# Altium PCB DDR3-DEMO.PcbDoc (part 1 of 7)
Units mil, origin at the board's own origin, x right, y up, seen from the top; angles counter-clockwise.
Board outline 2827 x 2165.35 mil, 8 copper layers (TOP, GND02, ART03, ART04, PWR05, ART06, GND07, BOTTOM); 111 components, 133 nets, 5542 pads, 873 vias.
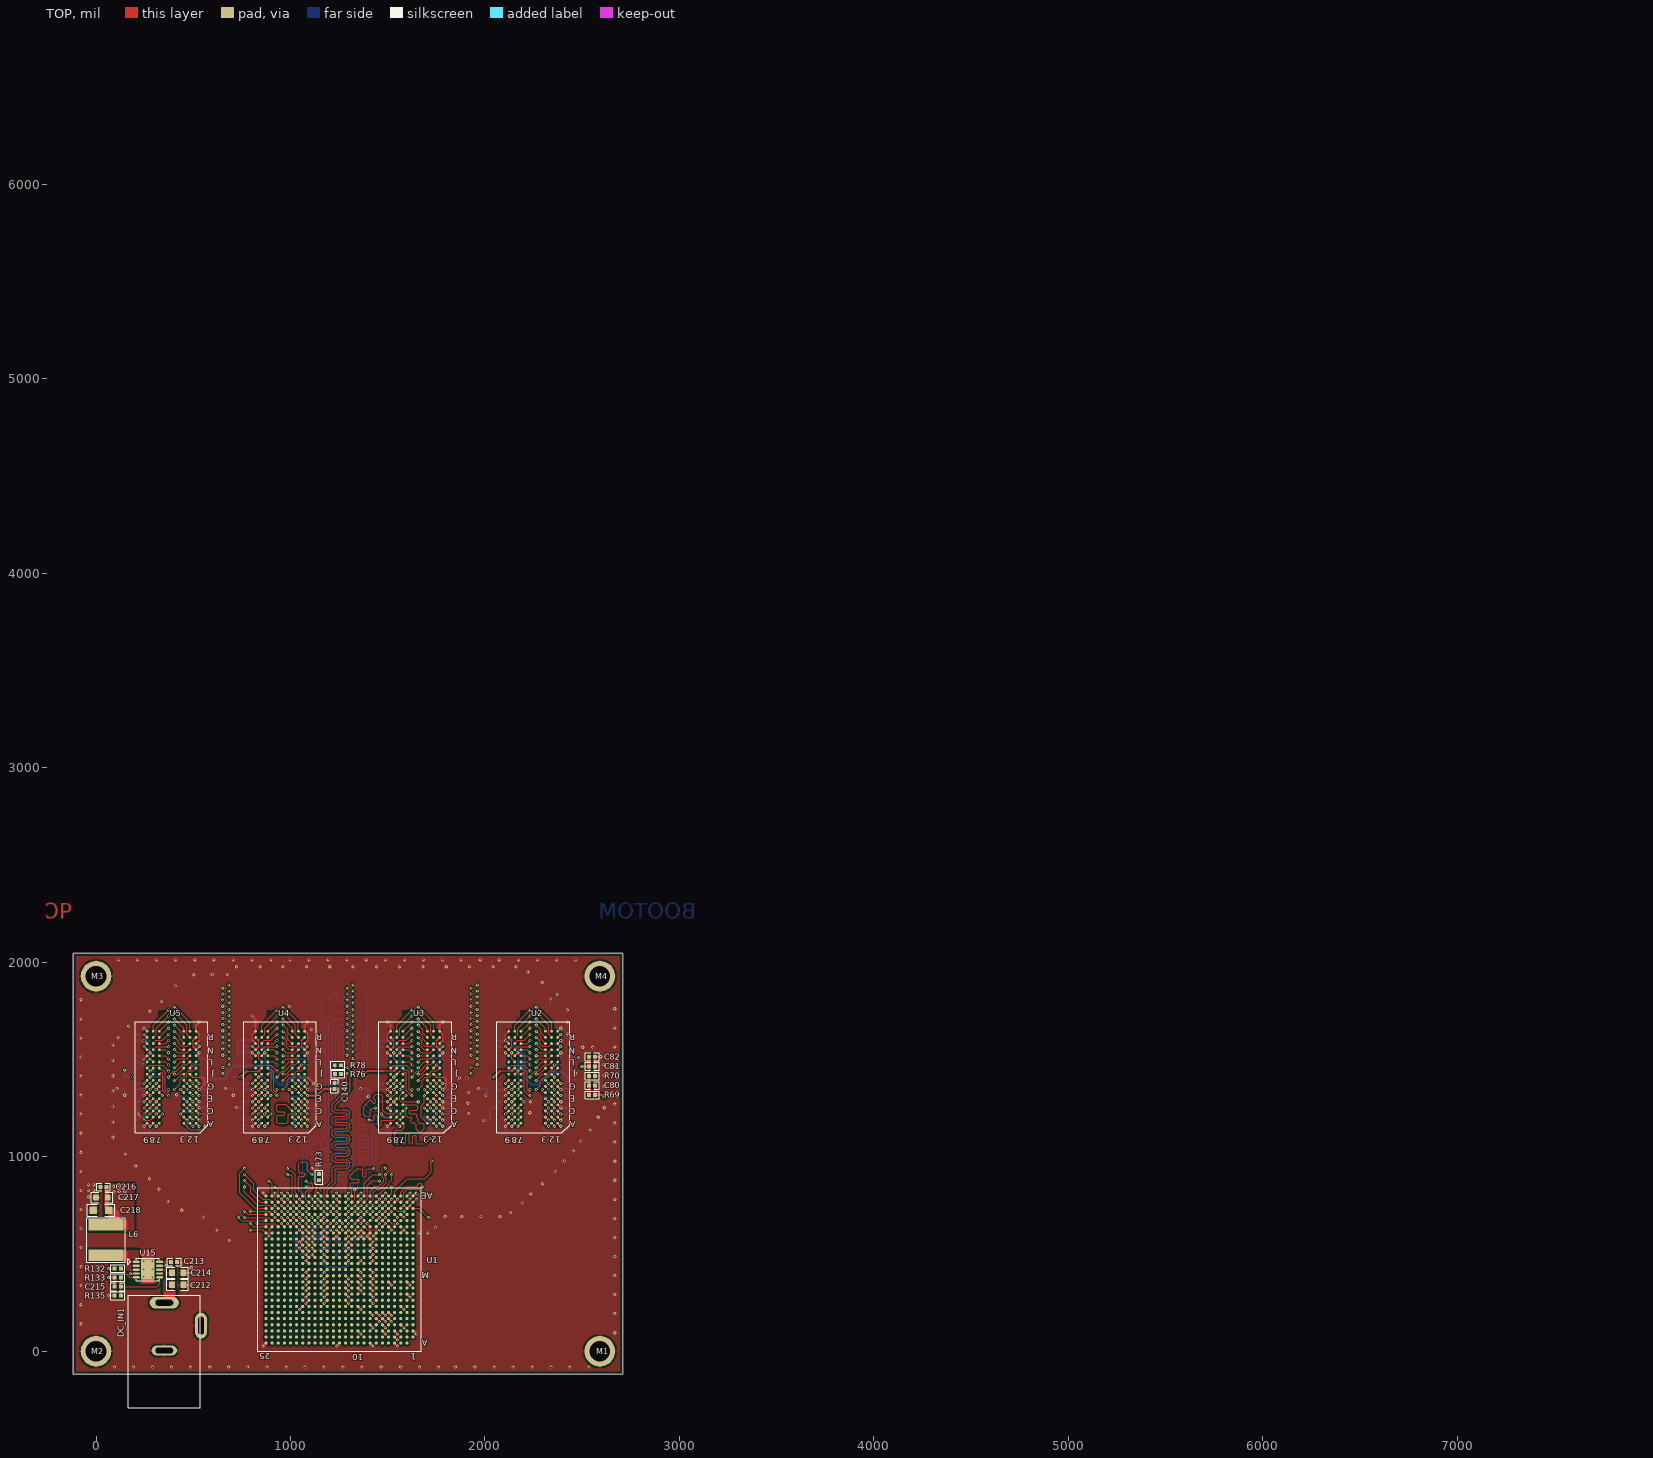
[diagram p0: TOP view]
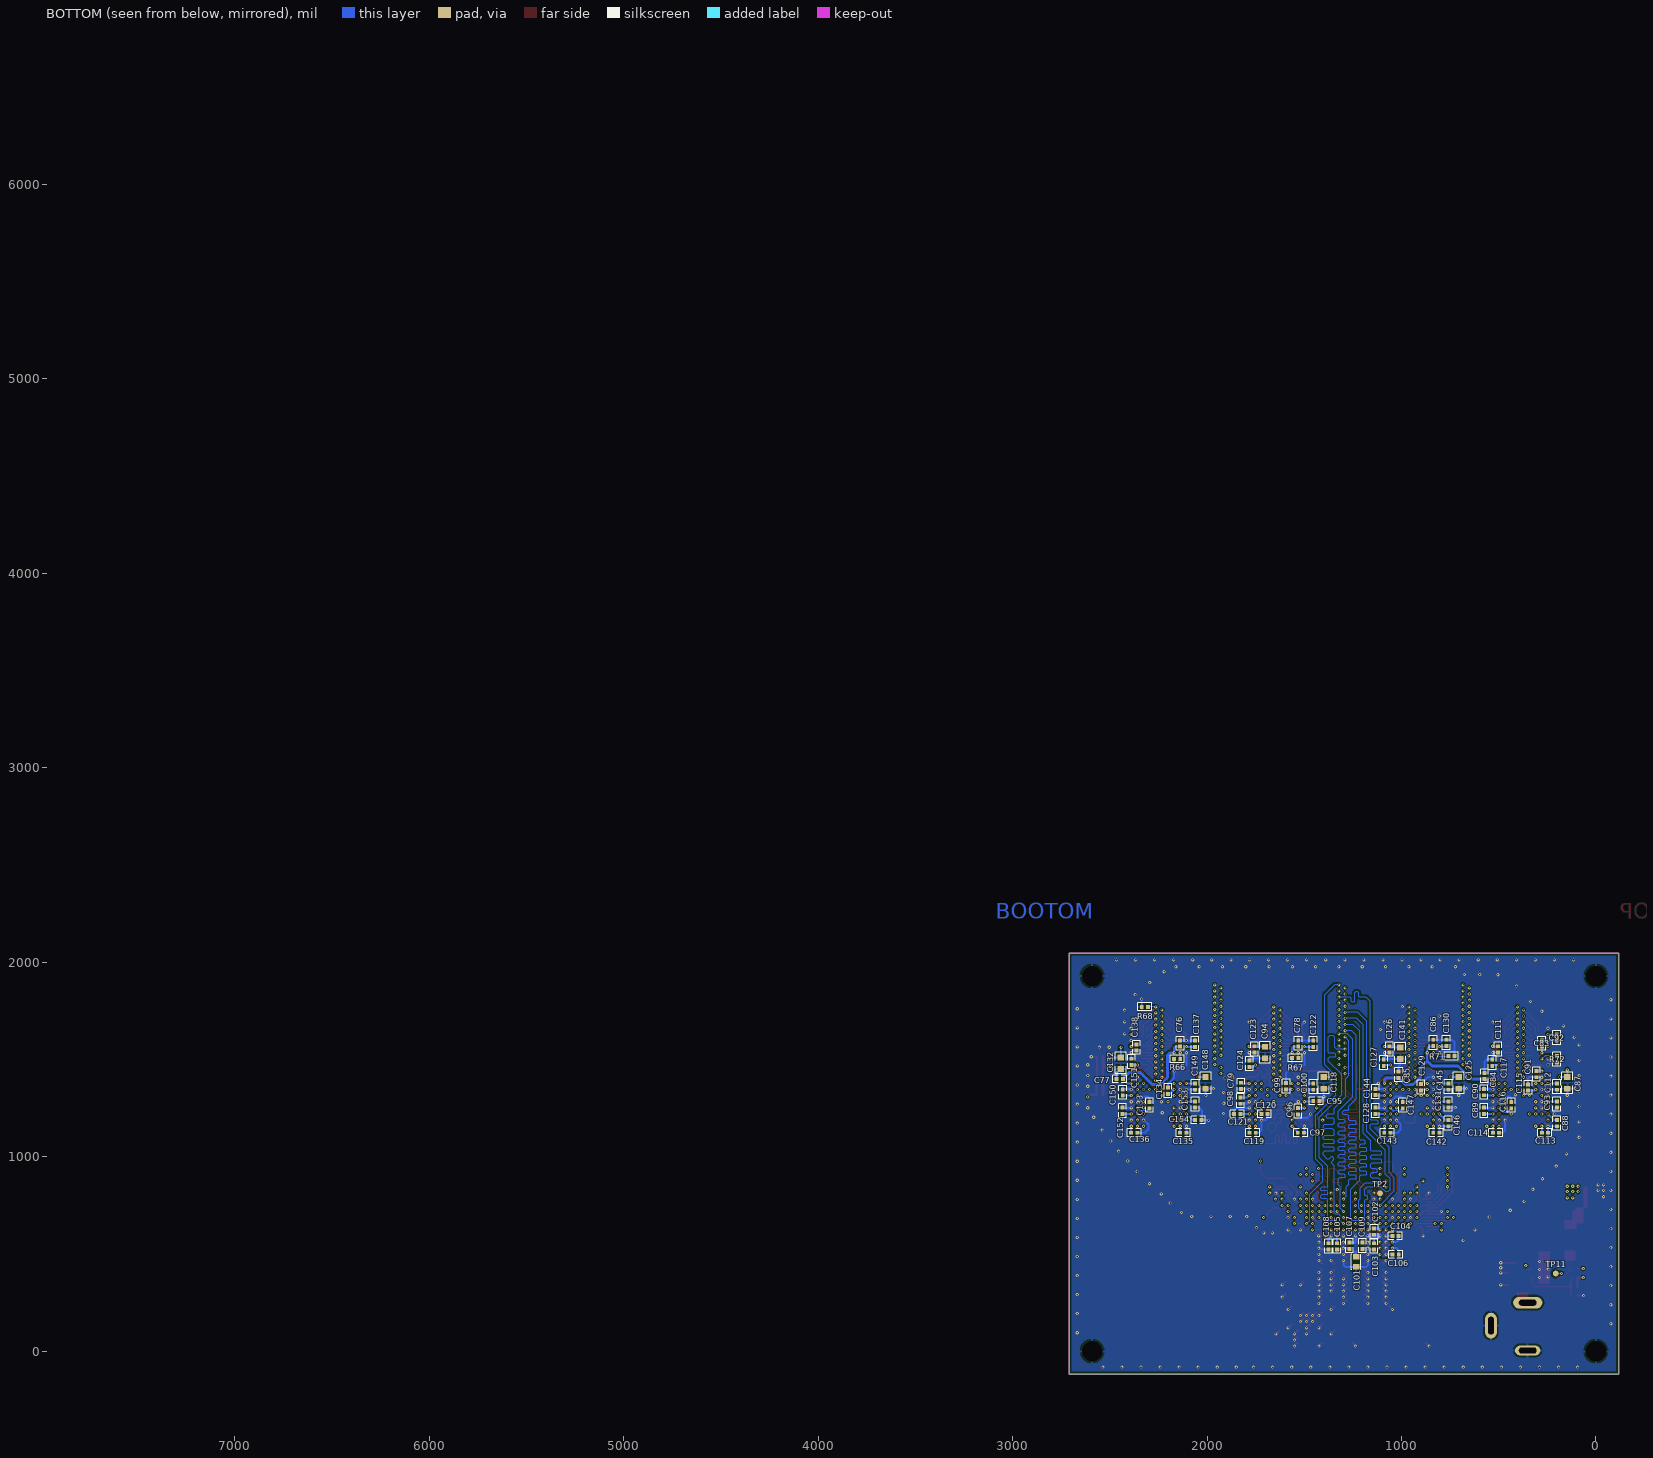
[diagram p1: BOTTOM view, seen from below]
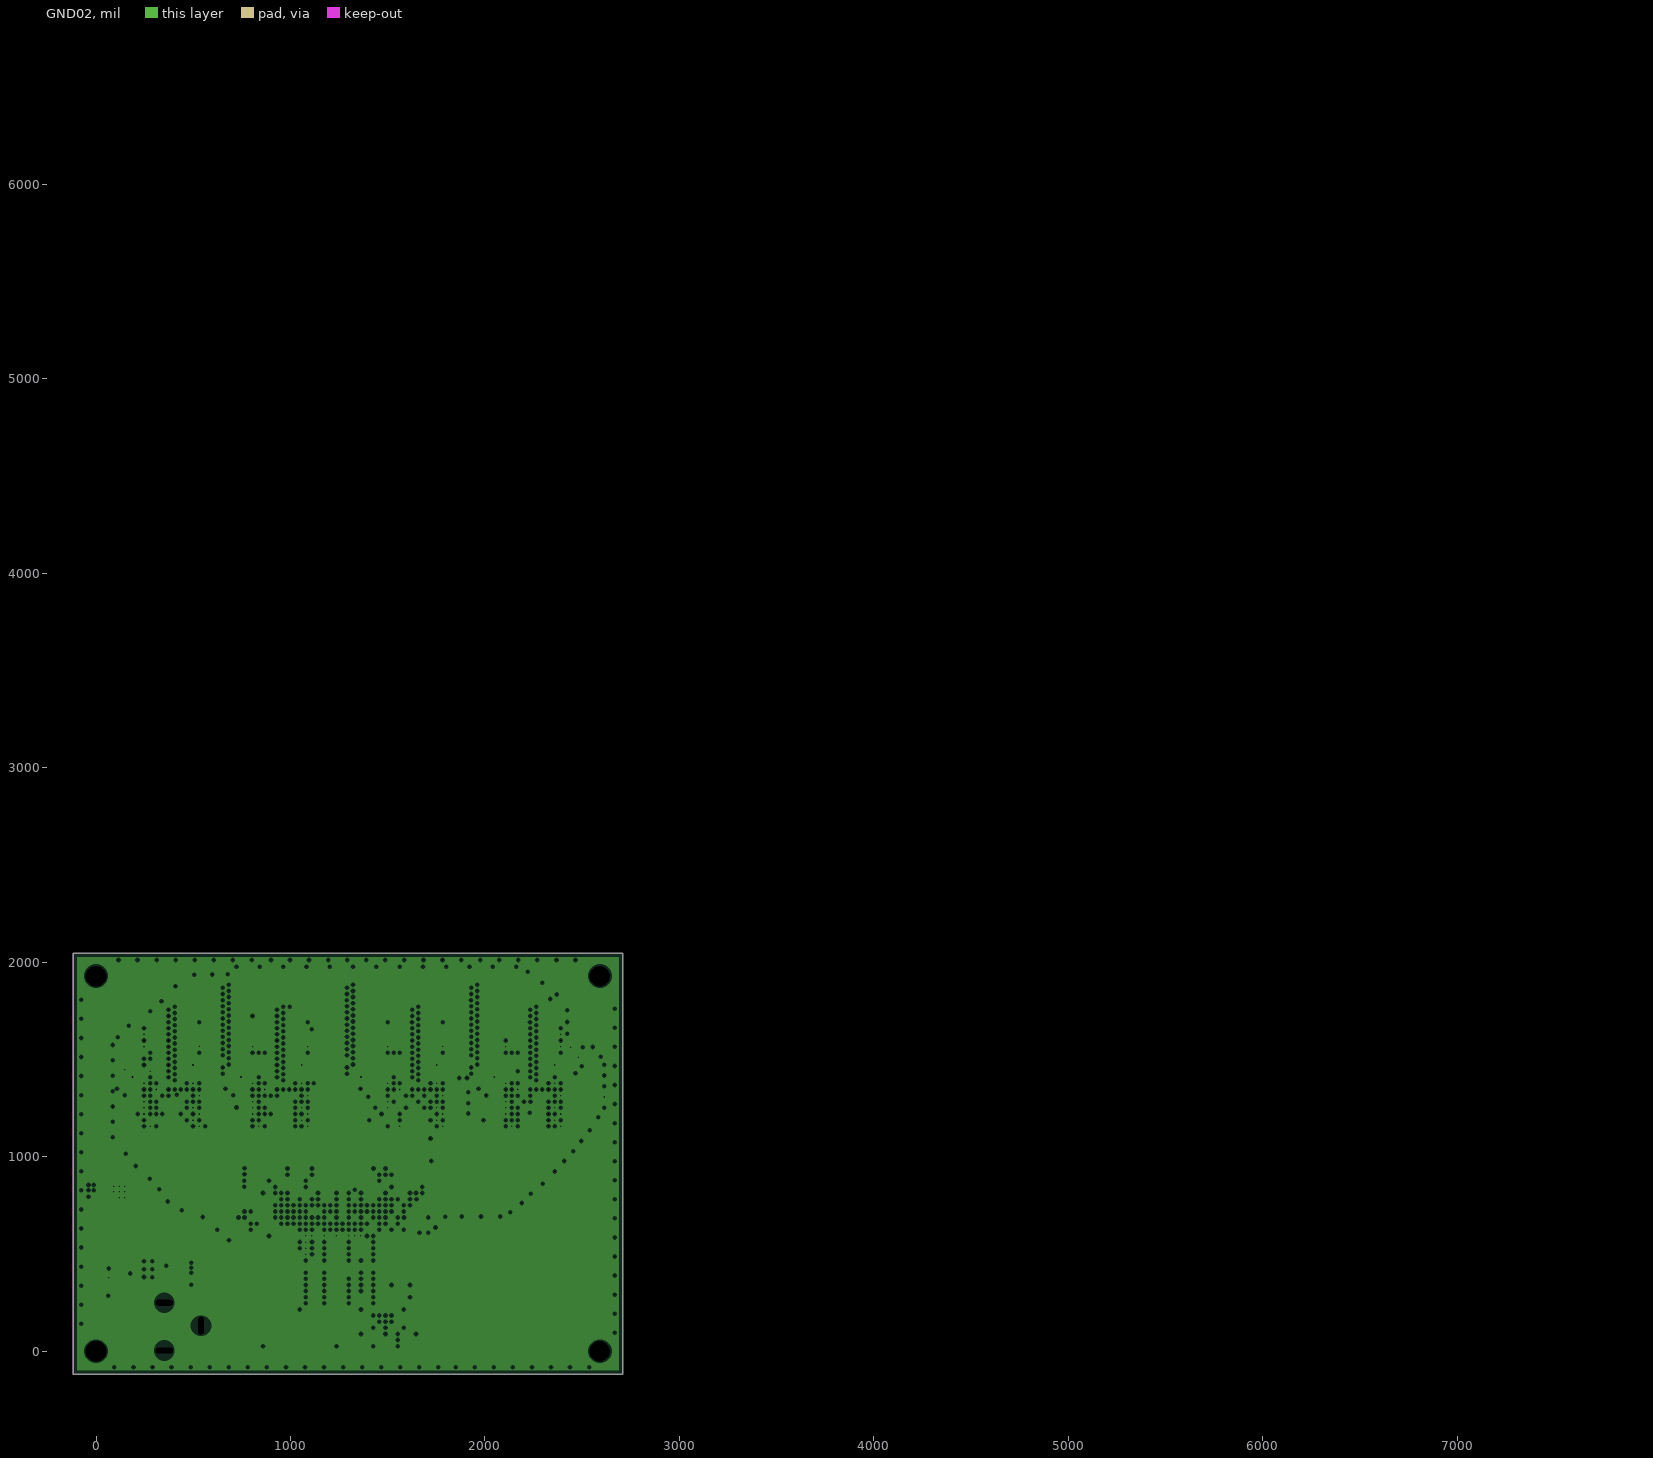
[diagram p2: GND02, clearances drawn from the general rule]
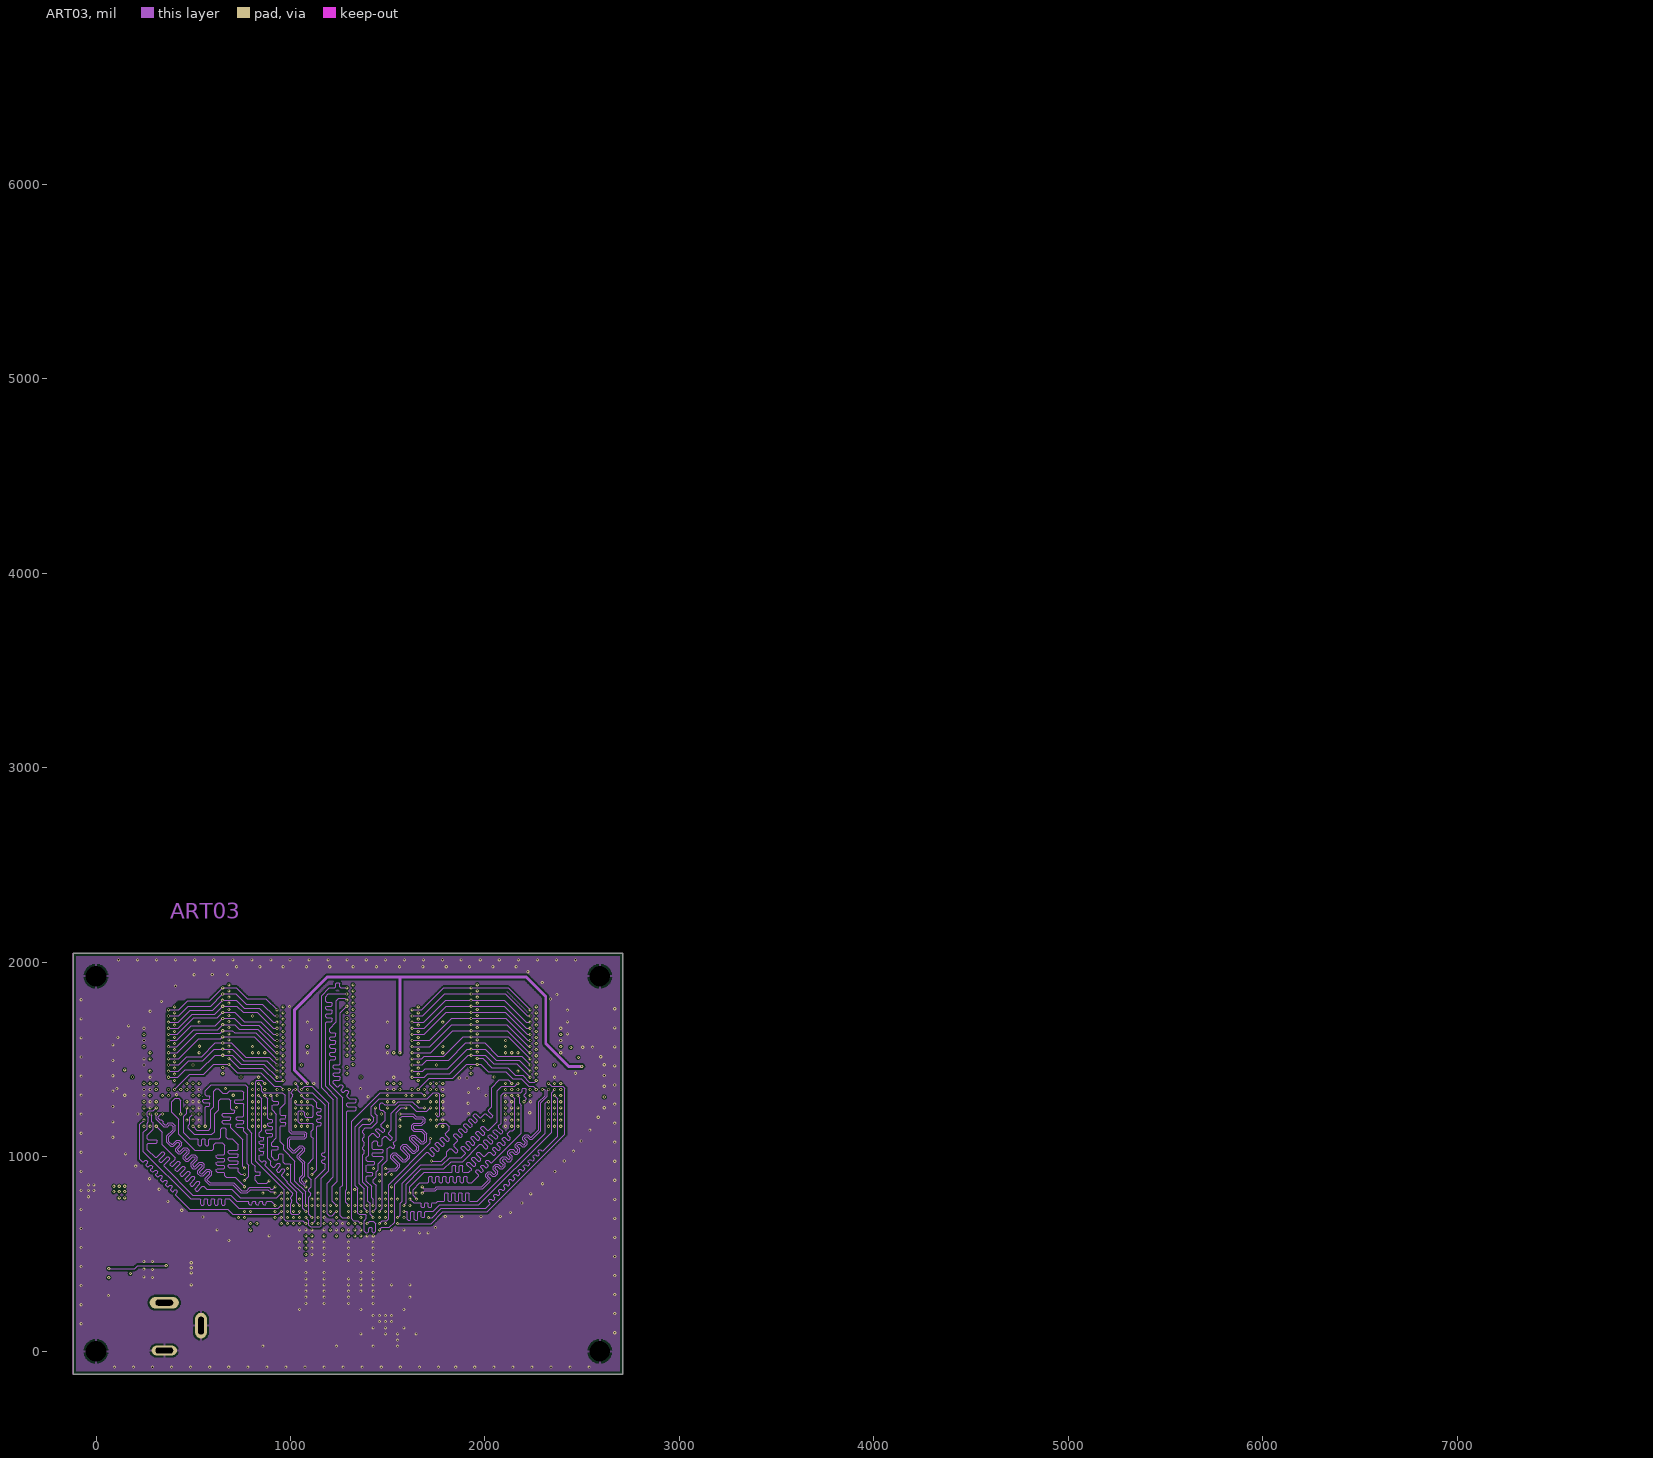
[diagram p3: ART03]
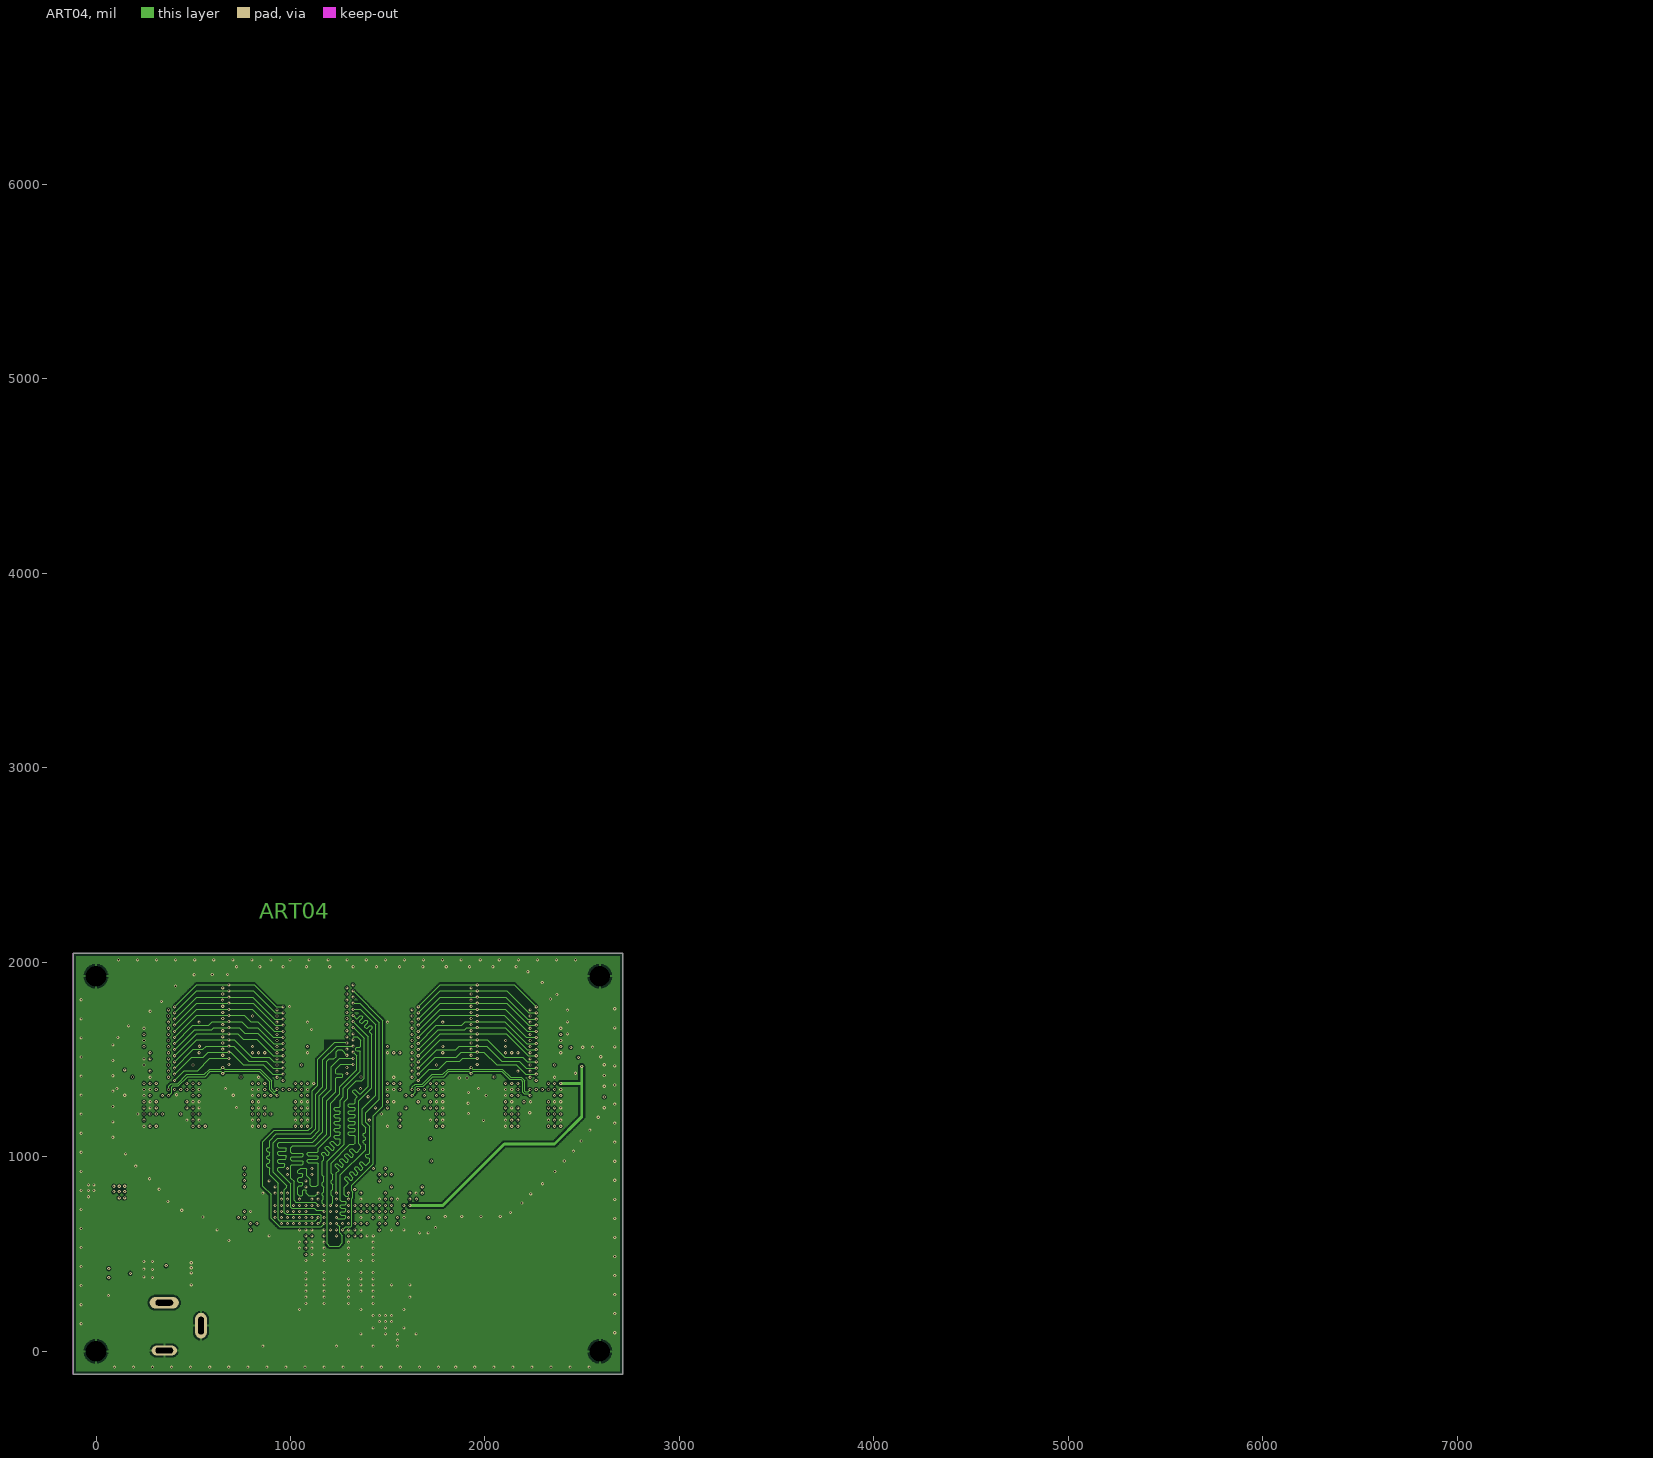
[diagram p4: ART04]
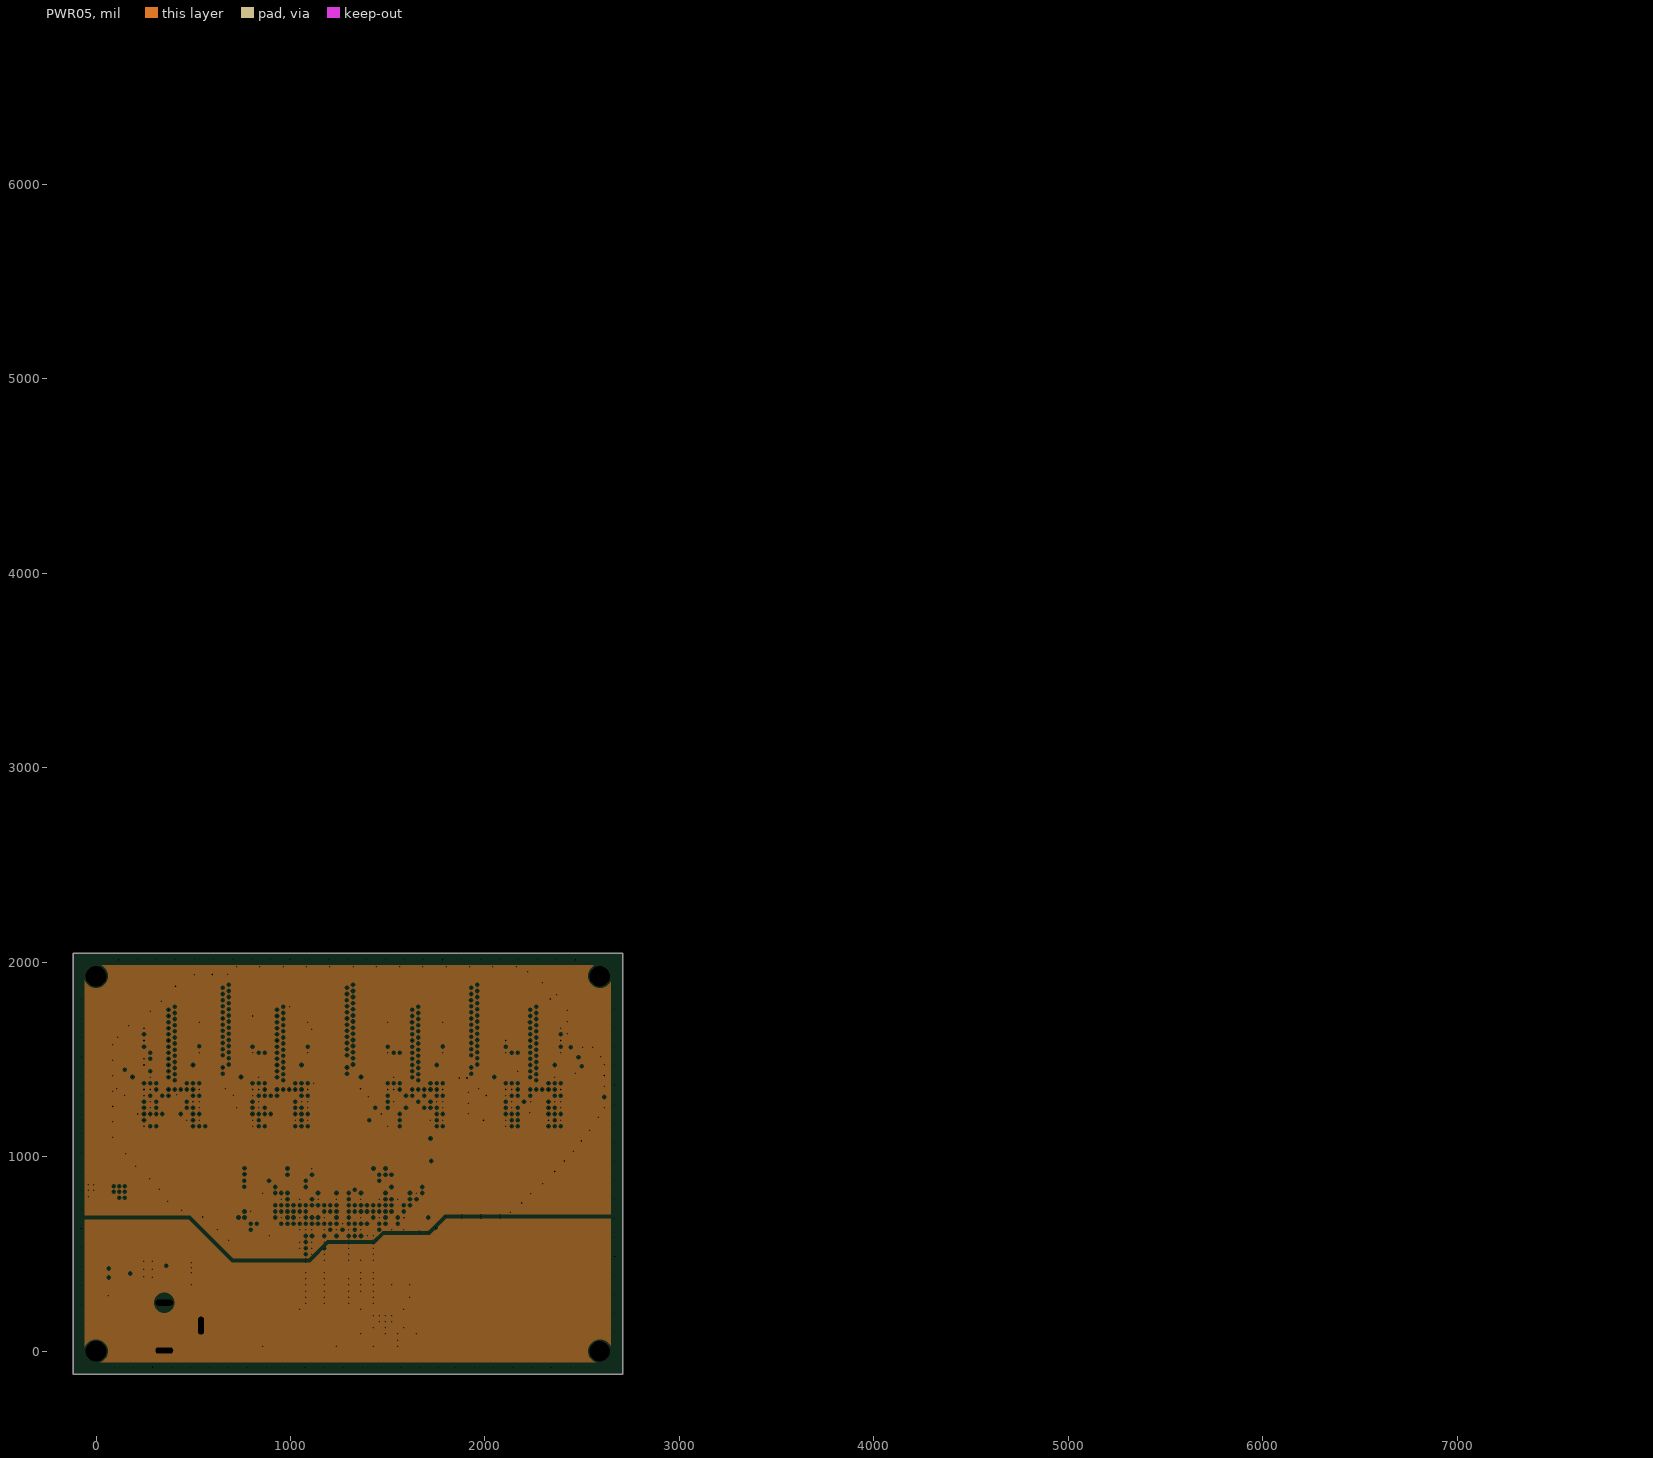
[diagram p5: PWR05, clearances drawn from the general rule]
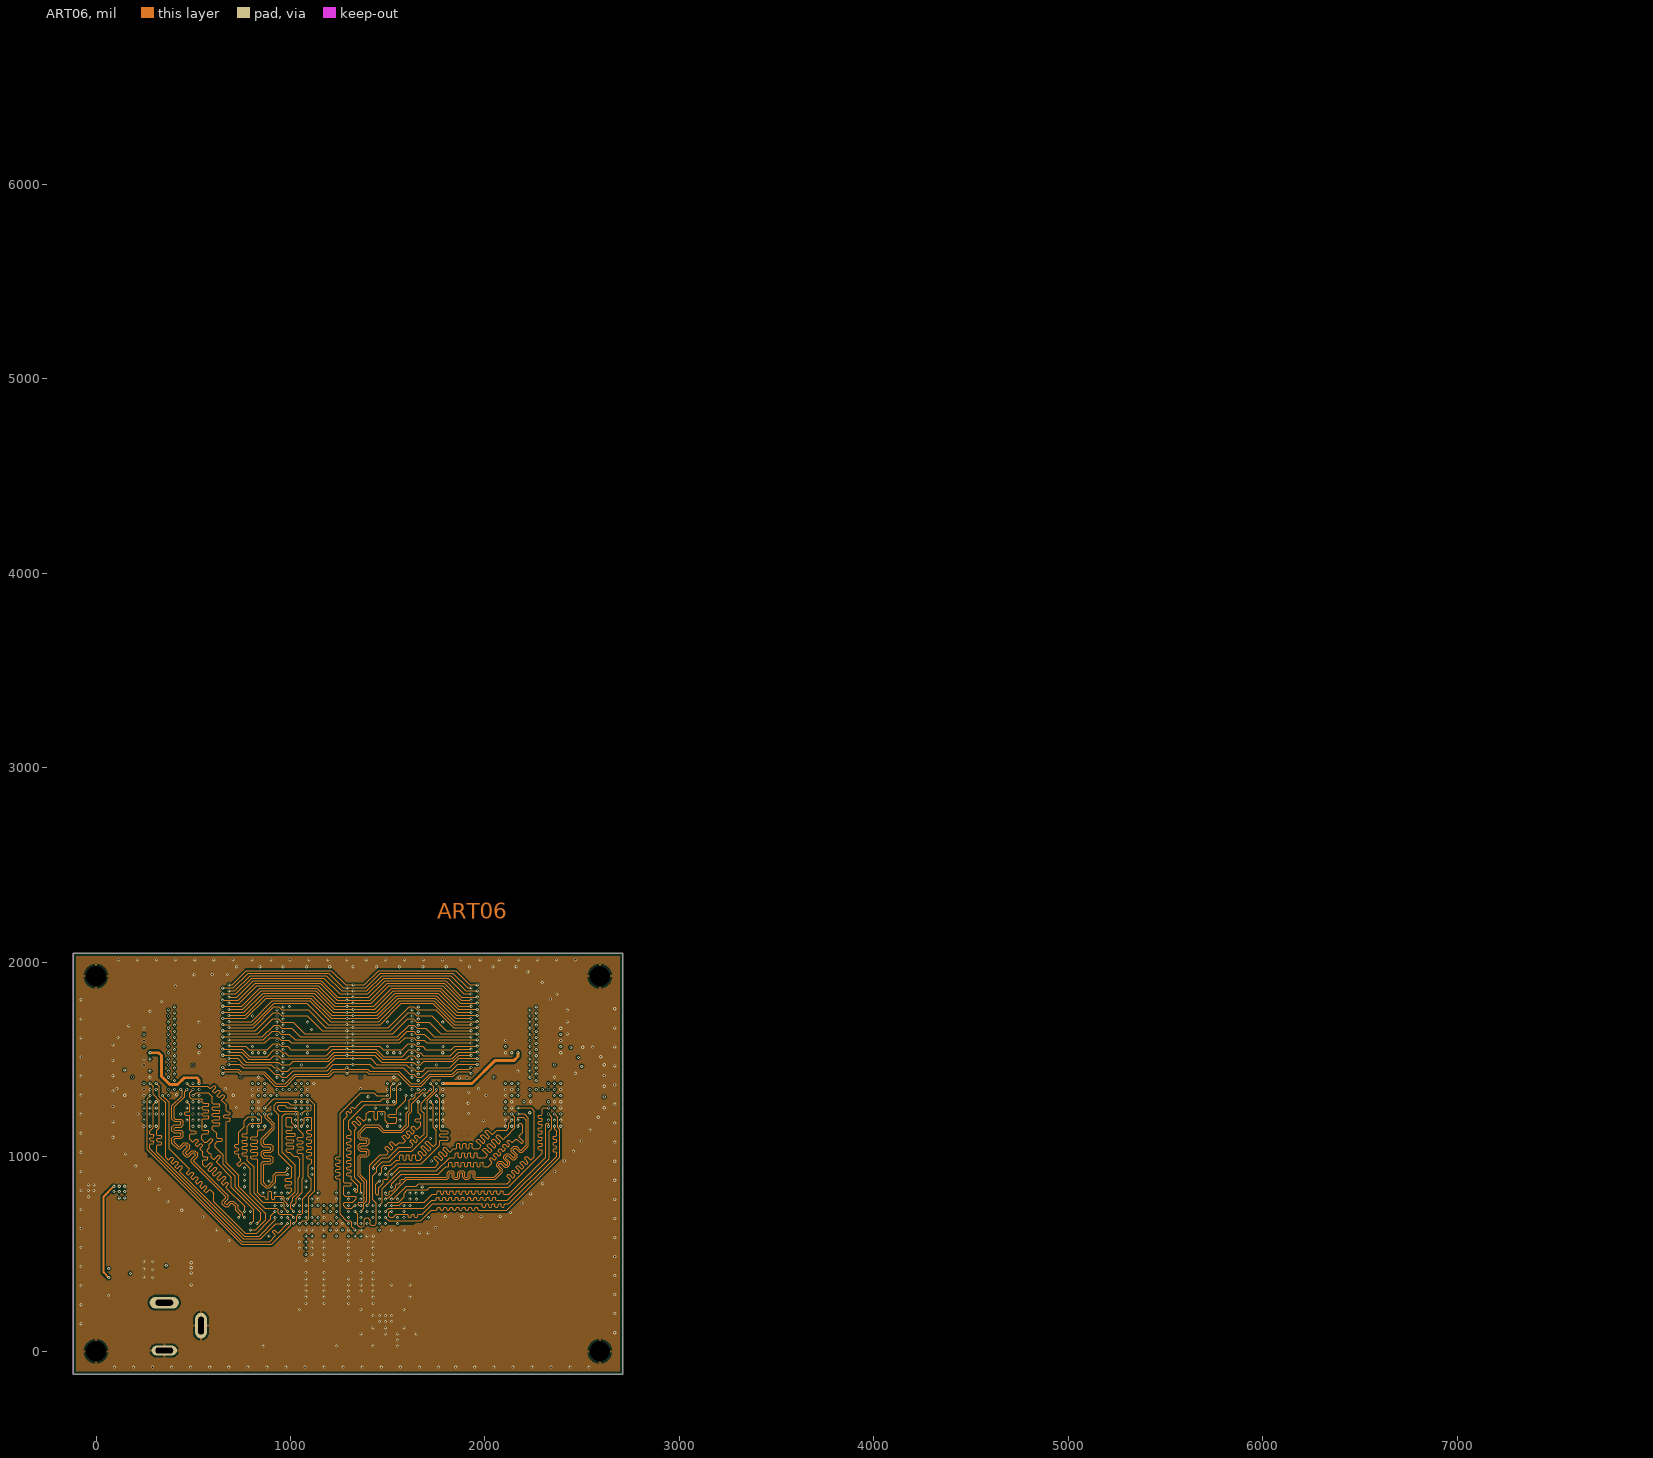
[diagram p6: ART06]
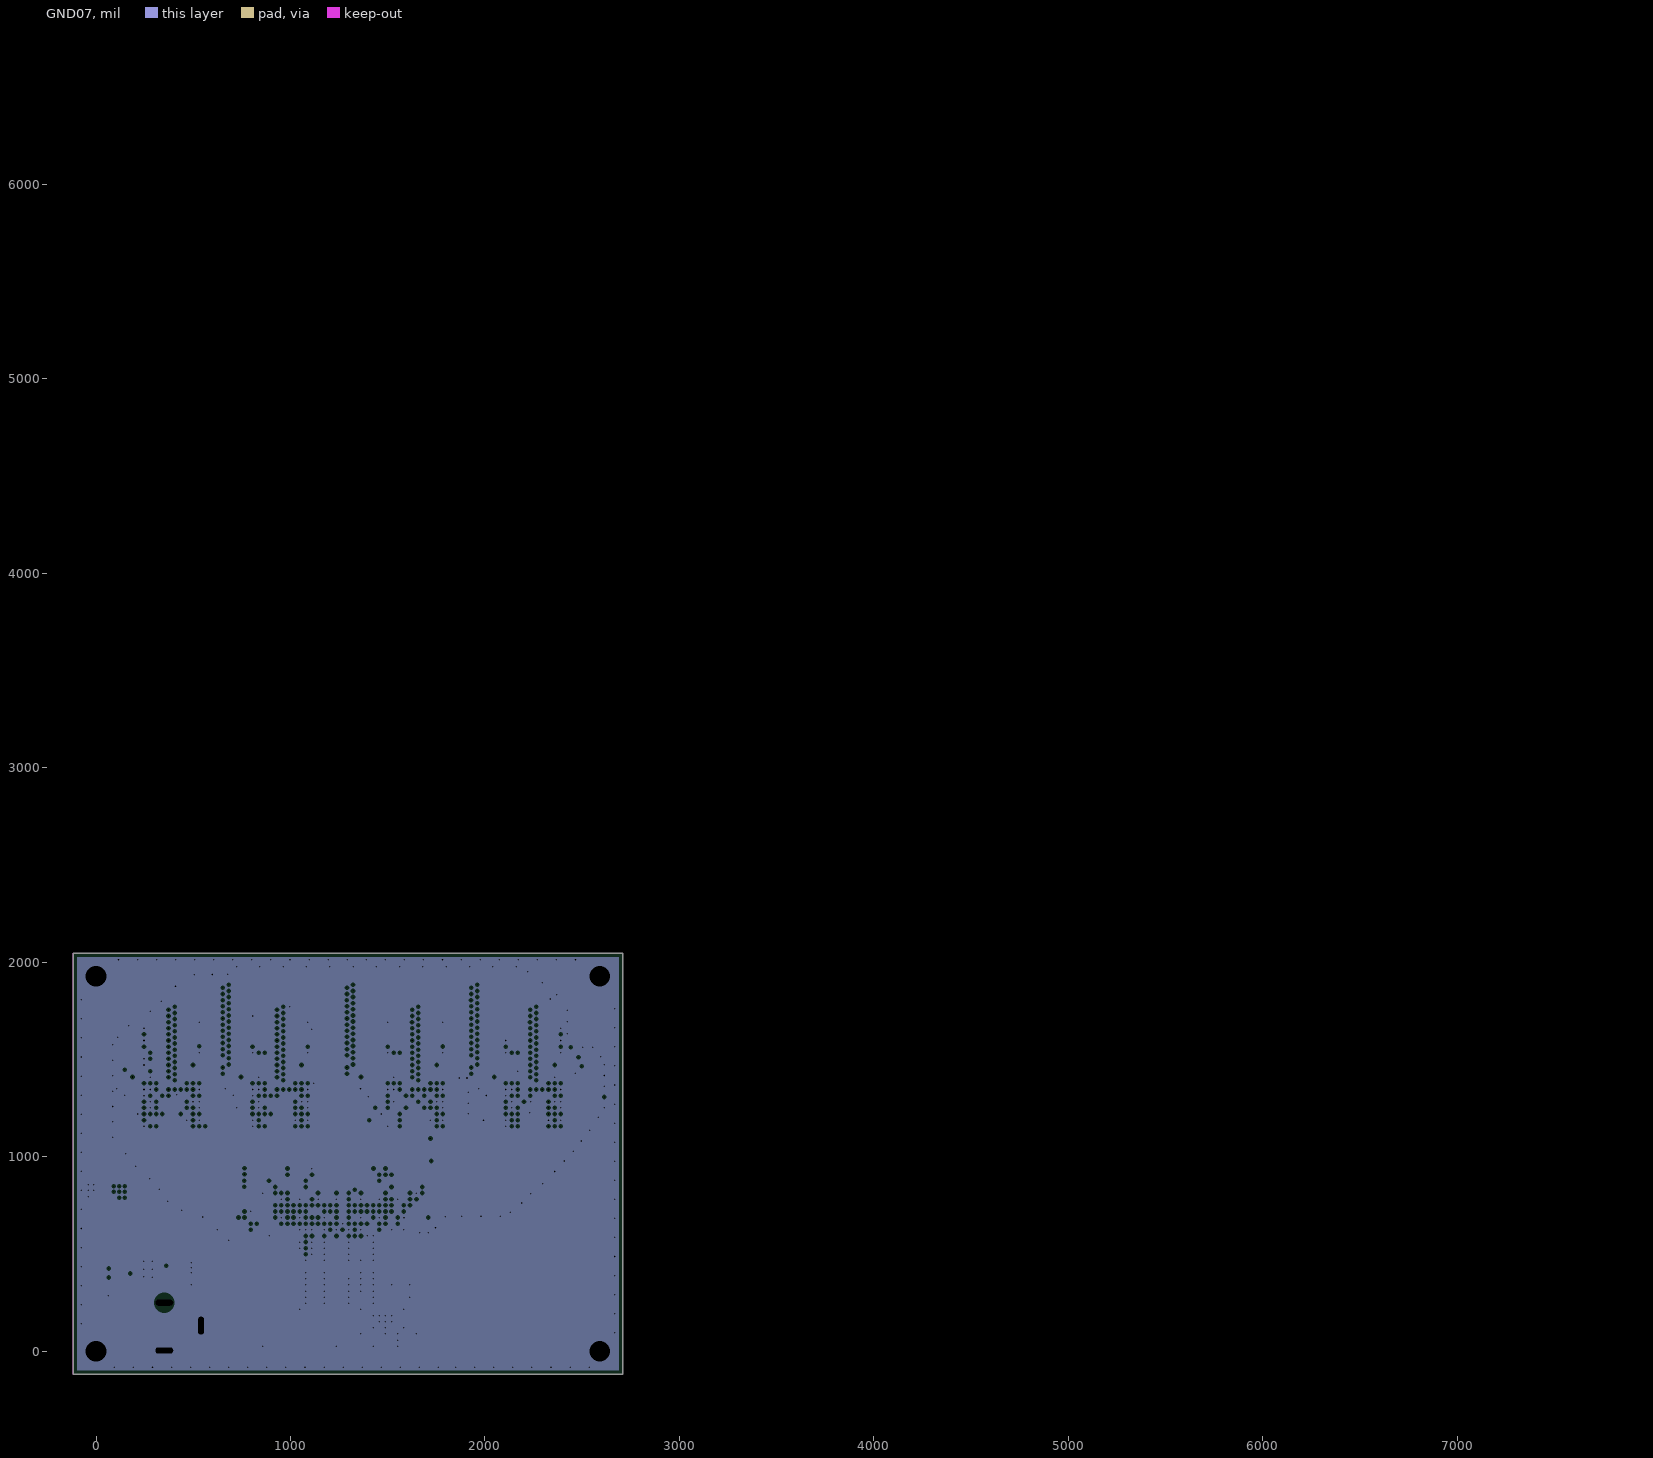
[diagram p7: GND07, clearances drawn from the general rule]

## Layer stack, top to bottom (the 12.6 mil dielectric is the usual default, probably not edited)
TOP: signal copper 1.4
Dielectric: core 12.6, FR-4, Dk 4.8
GND02: plane copper 1.4, net GND
Dielectric: prepreg 12.6, FR-4, Dk 4.8
ART03: signal copper 1.4
Dielectric: core 12.6, FR-4, Dk 4.8
ART04: signal copper 1.4
Dielectric: prepreg 12.6, FR-4, Dk 4.8
PWR05: plane copper 1.4, net VDD_1V5
Dielectric: core 12.6, FR-4, Dk 4.8
ART06: signal copper 1.4
Dielectric: prepreg 12.6, FR-4, Dk 4.8
GND07: plane copper 1.4, net GND
Dielectric: core 12.6, FR-4, Dk 4.8
BOTTOM: signal copper 1.4

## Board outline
-118.11,-118.11 2708.89,-118.11 2708.89,2047.24 -118.11,2047.24

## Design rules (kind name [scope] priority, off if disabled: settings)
Clearance [istrack>(InDifferentialPairClass('All Differential Pairs')) vs (IsTrack)] p1 off: gap=12
Clearance via-poly [isvia vs inpoly] p2: gap=5
Clearance poly [(InPolygon)] p3: gap=10
Clearance All [All] p4: gap=4.5
DiffPairsRouting DiffPair_100DiffPairsRouting [InDifferentialPairClass('100')] p1: maxlimit=9 minlimit=6 mostfreqgap=9 toplayer_mingap=9 midlayer1_maxgap=6 midlayer1_prefgap=6 midlayer2_maxgap=6 midlayer2_prefgap=6 midlayer3_mingap=7 midlayer3_maxgap=7 midlayer3_prefgap=7 bottomlayer_mingap=9 maxuncoupledlength=500
MatchedLengths DiffPair_100MatchedLengths [InDifferentialPairClass('100')] p1: tolerance=1000 checknetsindiffpair=TRUE checkdiffpairvsdiffpair=TRUE checkothers=TRUE
PlaneClearance [All] p1: clearance=8
PlaneConnect [All] p1: planeconnectstyle=Direct reliefexpansion=6 reliefentries=4 reliefconductorwidth=10 reliefairgap=8
PolygonConnect PolygonConnect_VIA [ISVIA] p1: connectstyle=Direct reliefconductorwidth=10 reliefentries=4 polygonreliefangle="90 Angle"
PolygonConnect PolygonConnect-ALL [All] p2: connectstyle=Relief reliefconductorwidth=10 reliefentries=4 polygonreliefangle="90 Angle"
RoutingVias [All] p1: holewidth=8 width=16 viastyle="Through Hole" minholewidth=8 minwidth=16 maxholewidth=8 maxwidth=16
SilkscreenOverComponentPads [All] p1: minsilkscreentomaskgap=10
SolderMaskExpansion [All] p1: expansion=2.5
Width DiffPair_100Width [(InDifferentialPairClass('100'))] p1: maxlimit=5 minlimit=4.5 preferedwidth=5 toplayer_maxwidth=4.5 toplayer_prefwidth=4.5 midlayer1_maxwidth=4.5 midlayer1_prefwidth=4.5 midlayer2_maxwidth=4.5 midlayer2_prefwidth=4.5 midlayer3_minwidth=5 bottomlayer_maxwidth=4.5 bottomlayer_prefwidth=4.5 minimp=50.000000 maximp=50.000000 favimp=50.000000
Width PWR [InNetClass('PWR')] p2: maxlimit=60 minlimit=10 preferedwidth=12
Width [All] p3: maxlimit=6 minlimit=4.1 preferedwidth=6 toplayer_minwidth=6 midlayer1_minwidth=6 midlayer2_minwidth=6 midlayer3_maxwidth=4.1 midlayer3_prefwidth=4.1 bottomlayer_minwidth=6 minimp=50.000000 maximp=50.000000 favimp=50.000000
24 further rules are at their usual default settings.

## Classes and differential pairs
net class PWR: GND VDD_1V5

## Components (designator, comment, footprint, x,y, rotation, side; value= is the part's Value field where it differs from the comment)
C76 "220nF" C0402 2137.93,1582.49 r90 bottom locked
C77 "220nF" C0402 2449.07,1399.35 r0 bottom locked
C78 "220nF" C0402 1530.92,1582.49 r90 bottom locked
C79 "220nF" C0402 1824.42,1364.78 r270 bottom locked
C80 "100nF" c0402 2550.56,1367.35 r180 top locked
C81 "100nF" c0402 2550.56,1465.35 r0 top locked
C82 "100nF" c0402 2550.56,1514.35 r0 top locked
C83 "220nF" C0402 278.42,1582.49 r90 bottom locked
C84 "220nF" C0402 573.42,1415.49 r90 bottom locked
C85 "220nF" C0402 1014.42,1421.49 r90 bottom locked
C86 "220nF" C0402 836.4,1585.63 r90 bottom locked
C87 "10uF" c0603 147.42,1380.35 r270 bottom locked
C88 "220nF" C0402 201.28,1173.21 r270 bottom locked
C89 "1nF" C0402 575.42,1236.49 r90 bottom locked
C90 "220nF" C0402 575.52,1332.49 r90 bottom locked
C91 "1nF" C0402 305.42,1425.21 r270 bottom locked
C92 "220nF" C0402 201.42,1613.21 r270 bottom locked
C93 "1nF" C0402 201.28,1269.21 r270 bottom locked
C94 "10uF" c0603 1701.42,1536.43 r270 bottom locked
C95 "220nF" C0402 1437.64,1286.35 r180 bottom locked
C96 "1nF" C0402 1531.42,1234.21 r270 bottom locked
C97 "220nF" C0402 1517.28,1123.59 r180 bottom locked
C98 "1nF" C0402 1828.02,1289.21 r270 bottom locked
C99 "220nF" C0402 1592.92,1362.49 r90 bottom locked
C100 "1nF" C0402 1453.78,1361.21 r270 bottom locked
C101 "22uF" 0603_cc 1233.42,459.76 r270 bottom locked
C102 "10nF" c0402 1140.42,615.49 r90 bottom locked
C103 "10nF" c0402 1141.42,539.21 r270 bottom locked
C104 "10nF" c0402 1031.03,593.13 r180 bottom locked
C105 "10nF" c0402 1331.42,539.21 r270 bottom locked
C106 "220nF" c0402 1030.28,498.35 r180 bottom locked
C107 "220nF" c0402 1266.42,542.21 r270 bottom locked
C108 "220nF" c0402 1375.42,539.35 r270 bottom locked
C109 "220nF" c0402 1200.42,542.21 r270 bottom locked
C111 "10uF" c0402 503.42,1552.21 r270 bottom locked
C112 "220nF" c0402 201.28,1361.21 r270 bottom locked
C113 "220nF" c0402 262.28,1123.59 r180 bottom locked
C114 "220nF" c0402 514.28,1123.59 r180 bottom locked
C115 "220nF" c0402 348.42,1356.49 r90 bottom
C116 "220nF" c0402 435.42,1265.49 r90 bottom locked
C117 "1nF" c0402 533.42,1483.49 r90 bottom locked
C118 "10uF" c0603 1399.92,1380.35 r270 bottom locked
C119 "220nF" C0402 1765.28,1123.59 r180 bottom locked
C120 "220nF" C0402 1704.28,1220.35 r180 bottom locked
C121 "220nF" C0402 1844.06,1220.35 r0 bottom locked
C122 "220nF" C0402 1453.92,1580.92 r90 bottom locked
C123 "220nF" C0402 1755.92,1552.21 r270 bottom
C124 "1nF" C0402 1781.15,1478.26 r90 bottom
C125 "10uF" c0603 705.4,1380.35 r270 bottom locked
C126 "220nF" C0402 1061.4,1552.21 r270 bottom locked
C127 "1nF" C0402 1091.4,1483.49 r90 bottom locked
C128 "220nF" C0402 1133.4,1236.49 r90 bottom locked
C129 "1nF" C0402 899.42,1357.35 r90 bottom locked
C130 "220nF" C0402 769.42,1585.63 r90 bottom locked
C131 "1nF" C0402 759.26,1269.21 r270 bottom locked
C132 "10uF" c0603 2443.42,1481.43 r270 bottom locked
C133 "220nF" C0402 2294.93,1265.49 r90 bottom locked
C134 "1nF" C0402 2200.42,1339.49 r90 bottom locked
C135 "220nF" C0402 2121.79,1123.59 r180 bottom locked
C136 "1nF" C0402 2373.79,1123.59 r180 bottom locked
C137 "220nF" C0402 2060.93,1580.92 r90 bottom locked
C138 "1nF" C0402 2362.93,1562.21 r270 bottom
C140 "100nF" c0402 1226.69,1364.21 r90 top locked
C141 "10uF" c0603 1006.42,1532.43 r270 bottom locked
C142 "220nF" C0402 820.28,1123.59 r180 bottom locked
C143 "220nF" C0402 1072.26,1123.59 r180 bottom locked
C144 "220nF" C0402 1133.5,1333.49 r90 bottom locked
C145 "220nF" C0402 759.26,1361.21 r270 bottom locked
C146 "220nF" C0402 759.26,1173.21 r270 bottom locked
C147 "1nF" C0402 993.4,1265.49 r90 bottom locked
C148 "10uF" c0603 2006.93,1380.35 r270 bottom locked
C149 "220nF" C0402 2060.79,1361.21 r270 bottom locked
C150 "100nF" C0402 2433.32,1330.78 r90 bottom locked
C151 "220nF" C0402 2388.16,1488.26 r90 bottom locked
C152 "220nF" C0402 2434.93,1236.49 r90 bottom locked
C153 "220nF" C0402 2060.79,1269.21 r270 bottom locked
C154 "1nF" C0402 2044.65,1189.35 r180 bottom locked
C212 "10uF" c0603 419.81,341.89 r0 top locked
C213 "1uF" c0402 401.03,459.89 r0 top locked
C214 "10uF" c0603 419.81,403.89 r0 top locked
C215 "5pF" C0402 111.75,332.22 r0 top locked
C216 "100nF" C0402 38.28,844.89 r180 top locked
C217 "10uF" c0603 30.42,791.35 r180 top locked
C218 "22uF" c0805 25.49,724.89 r180 top locked
DC_IN1 "CONN - PWR" dcj143x90h110 445.38,126.92 r180 top locked
L6 "2.2uH" l2_5r0x5r0_lqh 50.89,571.63 r180 top locked
M1 "HOLE2R7-4" HOLE2R7-4 2590.78,0 r0 top locked
M2 "HOLE2R7-4" HOLE2R7-4 0,0 r0 top locked
M3 "HOLE2R7-4" HOLE2R7-4 0,1929.13 r0 top locked
M4 "HOLE2R7-4" HOLE2R7-4 2590.78,1929.13 r0 top locked
R66 "240 Ohm" r0402 2153.56,1502.35 r270 bottom locked
R67 "240 Ohm" r0402 1546.56,1507.35 r270 bottom locked
R68 "10K" r0402 2319.56,1771.35 r270 bottom locked
R69 "470 Ohm" r0402 2550.56,1318.35 r90 top locked
R70 "470 Ohm" r0402 2550.56,1416.35 r270 top locked
R71 "240 Ohm" r0402 743.12,1517.35 r90 bottom locked
R72 "240 Ohm" r0402 201.28,1501.21 r180 bottom locked
R73 "240 Ohm" r0402 1146.42,895.49 r0 top locked
R76 "49.9" r0402 1244.28,1425.35 r90 top locked
R78 "49.9" r0402 1243.56,1470.63 r270 top locked
R132 "100KOhm" R0402 111.75,424.89 r270 top locked
R133 "300KOhm" R0402 111.75,378.56 r270 top locked
R135 "200KOhm" R0402 111.75,285.89 r90 top locked
TP2 "TP" TPC30B 1110.42,812.35 r90 bottom locked
TP11 "TP" TPC30B 206.89,399.89 r0 bottom locked
U1 "iMX6Q" BGA624_0P8_21X21 1251.9,419.9 r180 top locked
U2 "MT41J128M16HA-15E" bga96_0p8_9p15x14p15 2247.91,1409.13 r180 top locked
U3 "MT41J128M16HA-15E" bga96_0p8_9p15x14p15 1640.9,1409.13 r180 top locked
U4 "MT41J128M16HA-15E" bga96_0p8_9p15x14p15 946.38,1409.13 r180 top locked
U5 "MT41J128M16HA-15E" bga96_0p8_9p15x14p15 388.4,1409.13 r180 top locked
U15 "RT8068AZQW" DFN11CH8 266.87,420.52 r0 top locked

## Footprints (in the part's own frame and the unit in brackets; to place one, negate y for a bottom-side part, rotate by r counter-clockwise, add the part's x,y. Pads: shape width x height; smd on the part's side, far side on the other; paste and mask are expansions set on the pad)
0603_cc [mil] "0603_CC"
  rect 28x33 smd: 1(-25.59,0) 2(25.59,0)
  silkscreen extent -40,-25 40,25
bga96_0p8_9p15x14p15 [mil] "BGA96_0P8_9P15X14P15"
  round 14 smd: A1(-125.98,236.22) A2(-94.49,236.22) A3(-62.99,236.22) A7(62.99,236.22) A8(94.49,236.22) A9(125.98,236.22) B1(-125.98,204.72) B2(-94.49,204.72) B3(-62.99,204.72) B7(62.99,204.72) B8(94.49,204.72) B9(125.98,204.72) C1(-125.98,173.23) C2(-94.49,173.23) C3(-62.99,173.23) C7(62.99,173.23) C8(94.49,173.23) C9(125.98,173.23) D1(-125.98,141.73) D2(-94.49,141.73) D3(-62.99,141.73) D7(62.99,141.73) D8(94.49,141.73) D9(125.98,141.73) E1(-125.98,110.24) E2(-94.49,110.24) E3(-62.99,110.24) E7(62.99,110.24) E8(94.49,110.24) E9(125.98,110.24) F1(-125.98,78.74) F2(-94.49,78.74) F3(-62.99,78.74) F7(62.99,78.74) F8(94.49,78.74) F9(125.98,78.74) G1(-125.98,47.24) G2(-94.49,47.24) G3(-62.99,47.24) G7(62.99,47.24) G8(94.49,47.24) G9(125.98,47.24) H1(-125.98,15.75) H2(-94.49,15.75) H3(-62.99,15.75) H7(62.99,15.75) H8(94.49,15.75) H9(125.98,15.75) J1(-125.98,-15.75) J2(-94.49,-15.75) J3(-62.99,-15.75) J7(62.99,-15.75) J8(94.49,-15.75) J9(125.98,-15.75) K1(-125.98,-47.24) K2(-94.49,-47.24) K3(-62.99,-47.24) K7(62.99,-47.24) K8(94.49,-47.24) K9(125.98,-47.24) L1(-125.98,-78.74) L2(-94.49,-78.74) L3(-62.99,-78.74) L7(62.99,-78.74) L8(94.49,-78.74) L9(125.98,-78.74) M1(-125.98,-110.24) M2(-94.49,-110.24) M3(-62.99,-110.24) M7(62.99,-110.24) M8(94.49,-110.24) M9(125.98,-110.24) N1(-125.98,-141.73) N2(-94.49,-141.73) N3(-62.99,-141.73) N7(62.99,-141.73) N8(94.49,-141.73) N9(125.98,-141.73) P1(-125.98,-173.23) P2(-94.49,-173.23) P3(-62.99,-173.23) P7(62.99,-173.23) P8(94.49,-173.23) P9(125.98,-173.23) R1(-125.98,-204.72) R2(-94.49,-204.72) R3(-62.99,-204.72) R7(62.99,-204.72) R8(94.49,-204.72) R9(125.98,-204.72) T1(-125.98,-236.22) T2(-94.49,-236.22) T3(-62.99,-236.22) T7(62.99,-236.22) T8(94.49,-236.22) T9(125.98,-236.22)
  silkscreen extent -187,-286 187,286
BGA624_0P8_21X21 [mil] "BGA624_0P8_21X21"
  round 16 smd: A2(-346.46,377.95) A3(-314.96,377.95) A4(-283.46,377.95) A5(-251.97,377.95) A6(-220.47,377.95) A7(-188.98,377.95) A8(-157.48,377.95) A9(-125.98,377.95) A10(-94.49,377.95) A11(-62.99,377.95) A12(-31.5,377.95) A13(0,377.95) A14(31.5,377.95) A15(62.99,377.95) A16(94.49,377.95) A17(125.98,377.95) A18(157.48,377.95) A19(188.98,377.95) A20(220.47,377.95) A21(251.97,377.95) A22(283.46,377.95) A23(314.96,377.95) A24(346.46,377.95) A25(377.95,377.95) AA1(-377.95,-251.97) AA2(-346.46,-251.97) AA3(-314.96,-251.97) AA4(-283.46,-251.97) AA5(-251.97,-251.97) AA6(-220.47,-251.97) AA7(-188.98,-251.97) AA8(-157.48,-251.97) AA9(-125.98,-251.97) AA10(-94.49,-251.97) AA11(-62.99,-251.97) AA12(-31.5,-251.97) AA13(0,-251.97) AA14(31.5,-251.97) AA15(62.99,-251.97) AA16(94.49,-251.97) AA17(125.98,-251.97) AA18(157.48,-251.97) AA19(188.98,-251.97) AA20(220.47,-251.97) AA21(251.97,-251.97) AA22(283.46,-251.97) AA23(314.96,-251.97) AA24(346.46,-251.97) AA25(377.95,-251.97) AB1(-377.95,-283.46) AB2(-346.46,-283.46) AB3(-314.96,-283.46) AB4(-283.46,-283.46) AB5(-251.97,-283.46) AB6(-220.47,-283.46) AB7(-188.98,-283.46) AB8(-157.48,-283.46) AB9(-125.98,-283.46) AB10(-94.49,-283.46) AB11(-62.99,-283.46) AB12(-31.5,-283.46) AB13(0,-283.46) AB14(31.5,-283.46) AB15(62.99,-283.46) AB16(94.49,-283.46) AB17(125.98,-283.46) AB18(157.48,-283.46) AB19(188.98,-283.46) AB20(220.47,-283.46) AB21(251.97,-283.46) AB22(283.46,-283.46) AB23(314.96,-283.46) AB24(346.46,-283.46) AB25(377.95,-283.46) AC1(-377.95,-314.96) AC2(-346.46,-314.96) AC3(-314.96,-314.96) AC4(-283.46,-314.96) AC5(-251.97,-314.96) AC6(-220.47,-314.96) AC7(-188.98,-314.96) AC8(-157.48,-314.96) AC9(-125.98,-314.96) AC10(-94.49,-314.96) AC11(-62.99,-314.96) AC12(-31.5,-314.96) AC13(0,-314.96) AC14(31.5,-314.96) AC15(62.99,-314.96) AC16(94.49,-314.96) AC17(125.98,-314.96) AC18(157.48,-314.96) AC19(188.98,-314.96) AC20(220.47,-314.96) AC21(251.97,-314.96) AC22(283.46,-314.96) AC23(314.96,-314.96) AC24(346.46,-314.96) AC25(377.95,-314.96) AD1(-377.95,-346.46) AD2(-346.46,-346.46) AD3(-314.96,-346.46) AD4(-283.46,-346.46) AD5(-251.97,-346.46) AD6(-220.47,-346.46) AD7(-188.98,-346.46) AD8(-157.48,-346.46) AD9(-125.98,-346.46) AD10(-94.49,-346.46) AD11(-62.99,-346.46) AD12(-31.5,-346.46) AD13(0,-346.46) AD14(31.5,-346.46) AD15(62.99,-346.46) AD16(94.49,-346.46) AD17(125.98,-346.46) AD18(157.48,-346.46) AD19(188.98,-346.46) AD20(220.47,-346.46) AD21(251.97,-346.46) AD22(283.46,-346.46) AD23(314.96,-346.46) AD24(346.46,-346.46) AD25(377.95,-346.46) AE1(-377.95,-377.95) AE2(-346.46,-377.95) AE3(-314.96,-377.95) AE4(-283.46,-377.95) AE5(-251.97,-377.95) AE6(-220.47,-377.95) AE7(-188.98,-377.95) AE8(-157.48,-377.95) AE9(-125.98,-377.95) AE10(-94.49,-377.95) AE11(-62.99,-377.95) AE12(-31.5,-377.95) AE13(0,-377.95) AE14(31.5,-377.95) AE15(62.99,-377.95) AE16(94.49,-377.95) AE17(125.98,-377.95) AE18(157.48,-377.95) AE19(188.98,-377.95) AE20(220.47,-377.95) AE21(251.97,-377.95) AE22(283.46,-377.95) AE23(314.96,-377.95) AE24(346.46,-377.95) AE25(377.95,-377.95) B1(-377.95,346.46) B2(-346.46,346.46) B3(-314.96,346.46) B4(-283.46,346.46) B5(-251.97,346.46) B6(-220.47,346.46) B7(-188.98,346.46) B8(-157.48,346.46) B9(-125.98,346.46) B10(-94.49,346.46) B11(-62.99,346.46) B12(-31.5,346.46) B13(0,346.46) B14(31.5,346.46) B15(62.99,346.46) B16(94.49,346.46) B17(125.98,346.46) B18(157.48,346.46) B19(188.98,346.46) B20(220.47,346.46) B21(251.97,346.46) B22(283.46,346.46) B23(314.96,346.46) B24(346.46,346.46) B25(377.95,346.46) C1(-377.95,314.96) C2(-346.46,314.96) C3(-314.96,314.96) C4(-283.46,314.96) C5(-251.97,314.96) C6(-220.47,314.96) C7(-188.98,314.96) C8(-157.48,314.96) C9(-125.98,314.96) C10(-94.49,314.96) C11(-62.99,314.96) C12(-31.5,314.96) C13(0,314.96) C14(31.5,314.96) C15(62.99,314.96) C16(94.49,314.96) C17(125.98,314.96) C18(157.48,314.96) C19(188.98,314.96) C20(220.47,314.96) C21(251.97,314.96) C22(283.46,314.96) C23(314.96,314.96) C24(346.46,314.96) C25(377.95,314.96) D1(-377.95,283.46) D2(-346.46,283.46) D3(-314.96,283.46) D4(-283.46,283.46) D5(-251.97,283.46) D6(-220.47,283.46) D7(-188.98,283.46) D8(-157.48,283.46) D9(-125.98,283.46) D10(-94.49,283.46) D11(-62.99,283.46) D12(-31.5,283.46) D13(0,283.46) D14(31.5,283.46) D15(62.99,283.46) D16(94.49,283.46) D17(125.98,283.46) D18(157.48,283.46) D19(188.98,283.46) D20(220.47,283.46) D21(251.97,283.46) D22(283.46,283.46) D23(314.96,283.46) D24(346.46,283.46) D25(377.95,283.46) E1(-377.95,251.97) E2(-346.46,251.97) E3(-314.96,251.97) E4(-283.46,251.97) E5(-251.97,251.97) E6(-220.47,251.97) E7(-188.98,251.97) E8(-157.48,251.97) E9(-125.98,251.97) E10(-94.49,251.97) E11(-62.99,251.97) E12(-31.5,251.97) E13(0,251.97) E14(31.5,251.97) E15(62.99,251.97) E16(94.49,251.97) E17(125.98,251.97) E18(157.48,251.97) E19(188.98,251.97) E20(220.47,251.97) E21(251.97,251.97) E22(283.46,251.97) E23(314.96,251.97) E24(346.46,251.97) E25(377.95,251.97) F1(-377.95,220.47) F2(-346.46,220.47) F3(-314.96,220.47) F4(-283.46,220.47) F5(-251.97,220.47) F6(-220.47,220.47) F7(-188.98,220.47) F8(-157.48,220.47) F9(-125.98,220.47) F10(-94.49,220.47) F11(-62.99,220.47) F12(-31.5,220.47) F13(0,220.47) F14(31.5,220.47) F15(62.99,220.47) F16(94.49,220.47) F17(125.98,220.47) F18(157.48,220.47) F19(188.98,220.47) F20(220.47,220.47) F21(251.97,220.47) F22(283.46,220.47) F23(314.96,220.47) F24(346.46,220.47) F25(377.95,220.47) G1(-377.95,188.98) G2(-346.46,188.98) G3(-314.96,188.98) G4(-283.46,188.98) G5(-251.97,188.98) G6(-220.47,188.98) G7(-188.98,188.98) G8(-157.48,188.98) G9(-125.98,188.98) G10(-94.49,188.98) G11(-62.99,188.98) G12(-31.5,188.98) G13(0,188.98) G14(31.5,188.98) G15(62.99,188.98) G16(94.49,188.98) G17(125.98,188.98) G18(157.48,188.98) G19(188.98,188.98) G20(220.47,188.98) G21(251.97,188.98) G22(283.46,188.98) G23(314.96,188.98) G24(346.46,188.98) G25(377.95,188.98) H1(-377.95,157.48) H2(-346.46,157.48) H3(-314.96,157.48) H4(-283.46,157.48) H5(-251.97,157.48) H6(-220.47,157.48) H7(-188.98,157.48) H8(-157.48,157.48) H9(-125.98,157.48) H10(-94.49,157.48) H11(-62.99,157.48) H12(-31.5,157.48) H13(0,157.48) H14(31.5,157.48) H15(62.99,157.48) H16(94.49,157.48) H17(125.98,157.48) H18(157.48,157.48) H19(188.98,157.48) H20(220.47,157.48) H21(251.97,157.48) H22(283.46,157.48) H23(314.96,157.48) H24(346.46,157.48) H25(377.95,157.48) J1(-377.95,125.98) J2(-346.46,125.98) J3(-314.96,125.98) J4(-283.46,125.98) J5(-251.97,125.98) J6(-220.47,125.98) J7(-188.98,125.98) J8(-157.48,125.98) J9(-125.98,125.98) J10(-94.49,125.98) J11(-62.99,125.98) J12(-31.5,125.98) J13(0,125.98) J14(31.5,125.98) J15(62.99,125.98) J16(94.49,125.98) J17(125.98,125.98) J18(157.48,125.98) J19(188.98,125.98) J20(220.47,125.98) J21(251.97,125.98) J22(283.46,125.98) J23(314.96,125.98) J24(346.46,125.98) J25(377.95,125.98) K1(-377.95,94.49) K2(-346.46,94.49) K3(-314.96,94.49) K4(-283.46,94.49) K5(-251.97,94.49) K6(-220.47,94.49) K7(-188.98,94.49) K8(-157.48,94.49) K9(-125.98,94.49) K10(-94.49,94.49) K11(-62.99,94.49) K12(-31.5,94.49) K13(0,94.49) K14(31.5,94.49) K15(62.99,94.49) K16(94.49,94.49) K17(125.98,94.49) K18(157.48,94.49) K19(188.98,94.49) K20(220.47,94.49) K21(251.97,94.49) K22(283.46,94.49) K23(314.96,94.49) K24(346.46,94.49) K25(377.95,94.49) L1(-377.95,62.99) L2(-346.46,62.99) L3(-314.96,62.99) L4(-283.46,62.99) L5(-251.97,62.99) L6(-220.47,62.99) L7(-188.98,62.99) L8(-157.48,62.99) L9(-125.98,62.99) L10(-94.49,62.99) L11(-62.99,62.99) L12(-31.5,62.99) L13(0,62.99) L14(31.5,62.99) L15(62.99,62.99) L16(94.49,62.99) L17(125.98,62.99) L18(157.48,62.99) L19(188.98,62.99) L20(220.47,62.99) L21(251.97,62.99) L22(283.46,62.99) L23(314.96,62.99) L24(346.46,62.99) L25(377.95,62.99) M1(-377.95,31.5) M2(-346.46,31.5) M3(-314.96,31.5) M4(-283.46,31.5) M5(-251.97,31.5) M6(-220.47,31.5) M7(-188.98,31.5) M8(-157.48,31.5) M9(-125.98,31.5) M10(-94.49,31.5) M11(-62.99,31.5) M12(-31.5,31.5) M13(0,31.5) M14(31.5,31.5) M15(62.99,31.5) M16(94.49,31.5) M17(125.98,31.5) M18(157.48,31.5) M19(188.98,31.5) M20(220.47,31.5) M21(251.97,31.5) M22(283.46,31.5) M23(314.96,31.5) M24(346.46,31.5) M25(377.95,31.5) N1(-377.95,0) N2(-346.46,0) N3(-314.96,0) N4(-283.46,0) N5(-251.97,0) N6(-220.47,0) N7(-188.98,0) N8(-157.48,0) N9(-125.98,0) N10(-94.49,0) N11(-62.99,0) N12(-31.5,0) N13(0,0) N14(31.5,0) N15(62.99,0) N16(94.49,0) N17(125.98,0) N18(157.48,0) N19(188.98,0) N20(220.47,0) N21(251.97,0) N22(283.46,0) N23(314.96,0) N24(346.46,0) N25(377.95,0) P1(-377.95,-31.5) P2(-346.46,-31.5) P3(-314.96,-31.5) P4(-283.46,-31.5) P5(-251.97,-31.5) P6(-220.47,-31.5) P7(-188.98,-31.5) P8(-157.48,-31.5) P9(-125.98,-31.5) P10(-94.49,-31.5) P11(-62.99,-31.5) P12(-31.5,-31.5) P13(0,-31.5) P14(31.5,-31.5) P15(62.99,-31.5) P16(94.49,-31.5) P17(125.98,-31.5) P18(157.48,-31.5) P19(188.98,-31.5) P20(220.47,-31.5) P21(251.97,-31.5) P22(283.46,-31.5) P23(314.96,-31.5) P24(346.46,-31.5) P25(377.95,-31.5) R1(-377.95,-62.99) R2(-346.46,-62.99) R3(-314.96,-62.99) R4(-283.46,-62.99) R5(-251.97,-62.99) R6(-220.47,-62.99) R7(-188.98,-62.99) R8(-157.48,-62.99) R9(-125.98,-62.99) R10(-94.49,-62.99) R11(-62.99,-62.99) R12(-31.5,-62.99) R13(0,-62.99) R14(31.5,-62.99) R15(62.99,-62.99) R16(94.49,-62.99) R17(125.98,-62.99) R18(157.48,-62.99) R19(188.98,-62.99) R20(220.47,-62.99) R21(251.97,-62.99) R22(283.46,-62.99) R23(314.96,-62.99) R24(346.46,-62.99) R25(377.95,-62.99) T1(-377.95,-94.49) T2(-346.46,-94.49) T3(-314.96,-94.49) T4(-283.46,-94.49) T5(-251.97,-94.49) T6(-220.47,-94.49) T7(-188.98,-94.49) T8(-157.48,-94.49) T9(-125.98,-94.49) T10(-94.49,-94.49) T11(-62.99,-94.49) T12(-31.5,-94.49) T13(0,-94.49) T14(31.5,-94.49) T15(62.99,-94.49) T16(94.49,-94.49) T17(125.98,-94.49) T18(157.48,-94.49) T19(188.98,-94.49) T20(220.47,-94.49) T21(251.97,-94.49) T22(283.46,-94.49) T23(314.96,-94.49) T24(346.46,-94.49) T25(377.95,-94.49) U1(-377.95,-125.98) U2(-346.46,-125.98) U3(-314.96,-125.98) U4(-283.46,-125.98) U5(-251.97,-125.98) U6(-220.47,-125.98) U7(-188.98,-125.98) U8(-157.48,-125.98) U9(-125.98,-125.98) U10(-94.49,-125.98) U11(-62.99,-125.98) U12(-31.5,-125.98) U13(0,-125.98) U14(31.5,-125.98) U15(62.99,-125.98) U16(94.49,-125.98) U17(125.98,-125.98) U18(157.48,-125.98) U19(188.98,-125.98) U20(220.47,-125.98) U21(251.97,-125.98) U22(283.46,-125.98) U23(314.96,-125.98) U24(346.46,-125.98) U25(377.95,-125.98) V1(-377.95,-157.48) V2(-346.46,-157.48) V3(-314.96,-157.48) V4(-283.46,-157.48) V5(-251.97,-157.48) V6(-220.47,-157.48) V7(-188.98,-157.48) V8(-157.48,-157.48) V9(-125.98,-157.48) V10(-94.49,-157.48) V11(-62.99,-157.48) V12(-31.5,-157.48) V13(0,-157.48) V14(31.5,-157.48) V15(62.99,-157.48) V16(94.49,-157.48) V17(125.98,-157.48) V18(157.48,-157.48) V19(188.98,-157.48) V20(220.47,-157.48) V21(251.97,-157.48) V22(283.46,-157.48) V23(314.96,-157.48) V24(346.46,-157.48) V25(377.95,-157.48) W1(-377.95,-188.98) W2(-346.46,-188.98) W3(-314.96,-188.98) W4(-283.46,-188.98) W5(-251.97,-188.98) W6(-220.47,-188.98) W7(-188.98,-188.98) W8(-157.48,-188.98) W9(-125.98,-188.98) W10(-94.49,-188.98) W11(-62.99,-188.98) W12(-31.5,-188.98) W13(0,-188.98) W14(31.5,-188.98) W15(62.99,-188.98) W16(94.49,-188.98) W17(125.98,-188.98) W18(157.48,-188.98) W19(188.98,-188.98) W20(220.47,-188.98) W21(251.97,-188.98) W22(283.46,-188.98) W23(314.96,-188.98) W24(346.46,-188.98) W25(377.95,-188.98) Y1(-377.95,-220.47) Y2(-346.46,-220.47) Y3(-314.96,-220.47) Y4(-283.46,-220.47) Y5(-251.97,-220.47) Y6(-220.47,-220.47) Y7(-188.98,-220.47) Y8(-157.48,-220.47) Y9(-125.98,-220.47) Y10(-94.49,-220.47) Y11(-62.99,-220.47) Y12(-31.5,-220.47) Y13(0,-220.47) Y14(31.5,-220.47) Y15(62.99,-220.47) Y16(94.49,-220.47) Y17(125.98,-220.47) Y18(157.48,-220.47) Y19(188.98,-220.47) Y20(220.47,-220.47) Y21(251.97,-220.47) Y22(283.46,-220.47) Y23(314.96,-220.47) Y24(346.46,-220.47) Y25(377.95,-220.47)
  silkscreen extent -420,-420 420,420
C0402 [mm] "C0402"
  rect 0.51x0.51 smd: 1(-0.41,0) 2(0.41,0)
  silkscreen extent -0.91,-0.5 0.91,0.5
c0402 [mm] "C0402"
  rect 0.51x0.51 smd: 1(-0.41,0) 2(0.41,0)
  silkscreen extent -0.91,-0.5 0.91,0.5
c0603 [mil] "C0603"
  rect 29.92x31.5 smd: 1(-29.92,0) 2(29.92,0)
  silkscreen extent -55,-28 55,28
c0805 [mm] "C0805"
  rect 1x1 smd: 1(-1.001,0) 2(1.001,0)
  silkscreen extent -1.8,-0.8 1.8,0.8
dcj143x90h110 [mil] "DCJ143X90H110"
  oval 130x50 hole 30 slot 90 at 0 deg: 3(94.49,123.03)
  oval 60x132 hole 30 slot 90 at 90 deg: 4(-94.49,-4.9)
  oval 150x60 hole 30 slot 90 at 0 deg: 5(94.49,-123.03)
  silkscreen extent -91,-162 279,418
DFN11CH8 [mil] "DFN11CH8"
  oval 36x12 smd: 1(-59.98,39.37) 2(-59.98,19.37) 3(-59.98,-0.63) 4(-59.98,-20.64) 5(-59.98,-40.64) 6(60.02,-40.64) 7(60.02,-20.64) 8(60.02,-0.63) 9(60.02,19.37) 10(60.02,39.37)
  rect 69x104 smd: G1(0.02,0)
  silkscreen extent -105,-59 59,59
HOLE2R7-4 [mm] "HOLE2R7-4"
  round 4 / inner round 1.524 / far side round 1.524 hole 2.7: 1(0,0)
l2_5r0x5r0_lqh [mm] "L2_5R0X5R0_LQH"
  rect 4.57x1.52 smd: 1(0,2) 2(0,-2)
  silkscreen extent -2.5,-2.9 2.5,2.9
r0402 [mm] "R0402"
  rect 0.51x0.51 smd: 1(0,-0.41) 2(0,0.41)
  silkscreen extent -0.5,-0.91 0.5,0.91
R0402 [mm] "R0402"
  rect 0.51x0.51 smd: 1(0,-0.41) 2(0,0.41)
  silkscreen extent -0.5,-0.91 0.5,0.91
TPC30B [mil] "TPC30B"
  round 30 smd: 1(0,0)

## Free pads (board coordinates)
  round 5.12 on Drill Drawing: 1(3578.26,-285.31) 1(3578.26,-285.31) 1(3578.26,1711.69) 1(3578.26,4034.69) 1(3578.26,4478.91) 1(3578.26,4626.16) 1(3578.26,4782.85) 1(3578.26,4842.77) 1(3578.26,4842.77) 1(3578.26,4932.85) 1(3578.26,5082.85) 1(3578.26,5232.85) 1(3578.26,5382.85) 1(3578.26,5532.85) 1(3578.26,5683.25) 1(3578.26,5733.25) 1(3578.26,5883.25) 1(3578.26,6033.25) 1(3578.26,6183.25) 1(3578.26,6483.25) 1(3578.26,6533.25) 1(3578.26,6683.25) 1(3578.26,6683.25) 1(3703.09,4379.27) 1(3703.09,4379.27) 1(3703.09,4383.93) 1(3703.09,4383.93) 1(3704.09,4374.6) 1(3704.09,4374.6) 1(3704.09,4388.6) 1(3704.09,4388.6) 1(3706.09,4370.52) 1(3706.09,4370.52) 1(3706.09,4392.68) 1(3706.09,4392.68) 1(3709.09,4367.02) 1(3709.09,4367.02) 1(3709.09,4396.18) 1(3709.09,4396.18) 1(3712.59,4364.68) 1(3712.59,4364.68) 1(3712.59,4398.52) 1(3712.59,4398.52) 1(3716.59,4364.1) 1(3716.59,4364.1) 1(3716.59,4399.1) 1(3716.59,4399.1) 1(3720.59,4364.68) 1(3720.59,4364.68) 1(3720.59,4398.52) 1(3720.59,4398.52) 1(3724.09,4367.02) 1(3724.09,4367.02) 1(3724.09,4396.18) 1(3724.09,4396.18) 1(3727.09,4370.52) 1(3727.09,4370.52) 1(3727.09,4392.68) 1(3727.09,4392.68) 1(3729.09,4374.6) 1(3729.09,4374.6) 1(3729.09,4388.6) 1(3729.09,4388.6) 1(3730.09,4379.27) 1(3730.09,4379.27) 1(3730.09,4383.93) 1(3730.09,4383.93) 1(3739.59,4387.43) 1(3746.59,4364.1) 1(3746.59,4399.1) 1(3753.59,4387.43) 1(3768.09,4364.1) 1(3768.09,4382.18) 1(3768.09,4399.1) 1(3770.59,4385.1) 1(3770.59,4385.1) 1(3773.09,4386.85) 1(3773.09,4386.85) 1(3777.09,4387.43) 1(3777.09,4387.43) 1(3780.09,4386.85) 1(3780.09,4386.85) 1(3783.59,4384.52) 1(3783.59,4384.52) 1(3785.09,4364.1) 1(3785.09,4381.02) 1(3785.09,4381.02) 1(3798.09,4374.02) 1(3798.09,4374.02) 1(3798.09,4377.52) 1(3798.09,4377.52) 1(3799.09,4370.52) 1(3799.09,4370.52) 1(3799.09,4379.85) 1(3799.09,4381.02) 1(3799.09,4381.02) 1(3801.09,4385.1) 1(3801.09,4385.1) 1(3801.59,4367.02) 1(3801.59,4367.02) 1(3804.09,4386.85) 1(3804.09,4386.85) 1(3804.59,4364.68) 1(3804.59,4364.68) 1(3807.59,4387.43) 1(3807.59,4387.43) 1(3808.09,4364.1) 1(3808.09,4364.1) 1(3811.09,4386.27) 1(3811.09,4386.27) 1(3811.59,4365.27) 1(3811.59,4365.27) 1(3813.59,4383.93) 1(3813.59,4383.93) 1(3815.09,4368.77) 1(3815.09,4379.85) 1(3815.09,4379.85) 1(3829.59,4364.1) 1(3829.59,4382.77) 1(3829.59,4387.43) 1(3832.09,4385.1) 1(3832.09,4385.1) 1(3834.59,4386.85) 1(3834.59,4386.85) 1(3838.09,4387.43) 1(3838.09,4387.43) 1(3840.59,4386.85) 1(3840.59,4386.85) 1(3843.59,4385.1) 1(3885.09,4364.1) 1(3885.09,4399.1) 1(3885.09,4399.1) 1(3908.09,4364.1) 1(3908.09,4364.1) 1(3908.09,4399.1) 1(3917.59,4375.77) 1(3917.59,4375.77) 1(3918.59,4371.1) 1(3918.59,4371.1) 1(3918.59,4380.43) 1(3918.59,4380.43) 1(3920.59,4367.02) 1(3920.59,4367.02) 1(3920.59,4384.52) 1(3920.59,4384.52) 1(3923.59,4364.68) 1(3923.59,4364.68) 1(3923.59,4386.85) 1(3923.59,4386.85) 1(3926.04,-33.37) 1(3926.04,-33.37) 1(3926.04,-33.37) 1(3926.04,-33.37) 1(3926.04,76.48) 1(3926.04,76.48) 1(3926.04,186.32) 1(3926.04,186.32) 1(3926.04,296.16) 1(3926.04,296.16) 1(3926.04,406) 1(3926.04,406) 1(3926.04,515.85) 1(3926.04,515.85) 1(3926.04,625.69) 1(3926.04,625.69) 1(3926.04,625.69) 1(3926.04,625.69) 1(3926.04,625.69) 1(3926.04,625.69) 1(3926.59,4364.1) 1(3926.59,4364.1) 1(3926.59,4387.43) 1(3926.59,4387.43) 1(3926.82,838.73) 1(3926.82,838.73) 1(3926.82,948.57) 1(3926.82,1058.41) 1(3926.82,1168.25) 1(3926.82,1278.1) 1(3926.82,1387.94) 1(3926.82,1497.78) 1(3926.82,1497.78) 1(3926.82,1497.78) 1(3929.59,4364.68) 1(3929.59,4364.68) 1(3929.59,4386.85) 1(3929.59,4386.85) 1(3932.59,4367.02) 1(3932.59,4367.02) 1(3932.59,4384.52) 1(3932.59,4384.52) 1(3934.59,4371.1) 1(3934.59,4371.1) 1(3934.59,4380.43) 1(3934.59,4380.43) 1(3935.09,4375.77) 1(3935.09,4375.77) 1(3949.59,4387.43) 1(3956.59,4364.1) 1(3956.59,4399.1) 1(3963.59,4387.43) 1(3978.09,4374.02) 1(3978.09,4374.02) 1(3978.09,4377.52) 1(3978.09,4377.52) 1(3979.09,4370.52) 1(3979.09,4370.52) 1(3979.09,4379.85) 1(3979.09,4381.02) 1(3979.09,4381.02) 1(3981.09,4385.1) 1(3981.09,4385.1) 1(3981.59,4367.02) 1(3981.59,4367.02) 1(3984.09,4386.85) 1(3984.09,4386.85) 1(3984.59,4364.68) 1(3984.59,4364.68) 1(3987.59,4387.43) 1(3987.59,4387.43) 1(3988.09,4364.1) 1(3988.09,4364.1) 1(3991.09,4386.27) 1(3991.09,4386.27) 1(3991.59,4365.27) 1(3991.59,4365.27) 1(3993.59,4383.93) 1(3993.59,4383.93) 1(3995.09,4368.77) 1(3995.09,4379.85) 1(3995.09,4379.85) 1(4009.09,4368.18) 1(4010.59,4382.18) 1(4010.59,4382.18) 1(4011.59,4365.85) 1(4011.59,4365.85) 1(4011.59,4385.1) 1(4011.59,4385.1) 1(4012.59,4378.1) 1(4012.59,4378.1) 1(4013.59,4386.85) 1(4013.59,4386.85) 1(4015.09,4364.1) 1(4015.09,4364.1) 1(4016.59,4387.43) 1(4016.59,4387.43) 1(4018.09,4364.1) 1(4018.09,4364.1) 1(4019.59,4386.85) 1(4019.59,4386.85) 1(4021.09,4365.27) 1(4021.09,4365.27) 1(4021.59,4374.6) 1(4021.59,4374.6) 1(4022.59,4385.1) 1(4023.09,4367.02) 1(4023.09,4367.02) 1(4023.59,4372.85) 1(4023.59,4372.85) 1(4024.09,4369.35) 1(4024.09,4369.35) 1(4045.59,4363.52) 1(4045.59,4363.52) 1(4045.59,4364.68) 1(4045.59,4364.68) 1(4045.59,4379.27) 1(4045.59,4379.27) 1(4045.59,4380.43) 1(4045.59,4380.43) 1(4046.59,4362.93) 1(4046.59,4362.93) 1(4046.59,4365.27) 1(4046.59,4365.27) 1(4046.59,4378.68) 1(4046.59,4378.68) 1(4046.59,4381.02) 1(4046.59,4381.02) 1(4047.59,4363.52) 1(4047.59,4363.52) 1(4047.59,4364.68) 1(4047.59,4364.68) 1(4047.59,4379.27) 1(4047.59,4379.27) 1(4047.59,4380.43) 1(4047.59,4380.43) 1(4376.82,1347.78) 1(4376.82,1497.78) 1(4376.82,1497.78) 1(4376.82,1497.78) 1(4376.82,1497.78) 1(4376.82,1497.78) 1(4377.04,838.73) 1(4377.04,838.73) 1(4428.26,4782.85) 1(4428.26,4932.85) 1(4428.26,4932.85) 1(4428.26,5082.85) 1(4428.26,5082.85) 1(4428.26,5232.85) 1(4428.26,5232.85) 1(4428.26,5382.85) 1(4428.26,5382.85) 1(4428.26,5680.88) 1(4428.26,5733.25) 1(4428.26,5883.25) 1(4428.26,5883.25) 1(4428.26,6033.25) 1(4428.26,6033.25) 1(4428.26,6183.25) 1(4428.26,6183.25) 1(4428.26,6333.25) 1(4428.26,6333.25) 1(4428.26,6333.25) 1(4428.26,6483.25) 1(4428.26,6533.55) 1(4428.26,6683.25) 1(4456.45,-33.37) 1(4456.45,625.69) 1(4456.45,625.69) 1(4478.26,4808.05) 1(4478.26,4808.05) 1(4478.26,4808.05) 1(4478.26,4808.05) 1(4478.26,4908.05) 1(4478.26,4908.05) 1(4478.26,4908.05) 1(4478.26,4908.05) 1(4478.26,5108.05) 1(4478.26,5108.05) 1(4478.26,5208.05) 1(4478.26,5208.05) 1(4478.26,5258.05) 1(4478.26,5258.05) 1(4478.26,5258.05) 1(4478.26,5258.05) 1(4478.26,5358.05) 1(4478.26,5358.05) 1(4478.26,5358.05) 1(4478.26,5358.05) 1(4478.26,5408.05) 1(4478.26,5408.05) 1(4478.26,5508.05) 1(4478.26,5508.05) 1(4478.26,5758.05) 1(4478.26,5758.05) 1(4478.26,5758.05) 1(4478.26,5758.05) 1(4478.26,5858.05) 1(4478.26,5858.05) 1(4478.26,5858.05) 1(4478.26,5858.05) 1(4478.26,5908.05) 1(4478.26,5908.05) 1(4478.26,5908.05) 1(4478.26,5908.05) 1(4478.26,6008.05) 1(4478.26,6008.05) 1(4478.26,6008.05) 1(4478.26,6008.05) 1(4478.26,6058.05) 1(4478.26,6058.05) 1(4478.26,6158.05) 1(4478.26,6158.05) 1(4478.26,6208.05) 1(4478.26,6208.05) 1(4478.26,6308.05) 1(4478.26,6308.05) 1(4480.04,6363.05) 1(4480.04,6363.05) 1(4480.04,6463.05) 1(4480.04,6463.05) 1(4483.38,4817.29) 1(4483.38,4821.41) 1(4483.38,4825.53) 1(4483.38,4829.65) 1(4483.38,4833.77) 1(4483.38,4837.89) 1(4483.38,4842.01) 1(4483.38,4846.13) 1(4483.38,4850.25) 1(4483.38,4854.37) 1(4483.38,4858.49) 1(4483.38,4862.61) 1(4483.38,4866.73) 1(4483.38,4870.85) 1(4483.38,4874.97) 1(4483.38,4879.09) 1(4483.38,4883.21) 1(4483.38,4887.33) 1(4483.38,4891.45) 1(4483.38,4895.57) 1(4483.38,4899.69) 1(4483.38,5767.29) 1(4483.38,5771.41) 1(4483.38,5775.53) 1(4483.38,5779.65) 1(4483.38,5783.77) 1(4483.38,5787.89) 1(4483.38,5792.01) 1(4483.38,5796.13) 1(4483.38,5800.25) 1(4483.38,5804.37) 1(4483.38,5808.49) 1(4483.38,5812.61) 1(4483.38,5816.73) 1(4483.38,5820.85) 1(4483.38,5824.97) 1(4483.38,5829.09) 1(4483.38,5833.21) 1(4483.38,5837.33) 1(4483.38,5841.45) 1(4483.38,5845.57) 1(4483.38,5849.69) 1(4484.16,5918.07) 1(4484.16,5922.19) 1(4484.16,5926.31) 1(4484.16,5930.43) 1(4484.16,5934.55) 1(4484.16,5938.67) 1(4484.16,5942.79) 1(4484.16,5946.91) 1(4484.16,5951.03) 1(4484.16,5955.15) 1(4484.16,5959.27) 1(4484.16,5963.39) 1(4484.16,5967.51) 1(4484.16,5971.63) 1(4484.16,5975.75) 1(4484.16,5979.87) 1(4484.16,5983.99) 1(4484.16,5988.11) 1(4484.16,5992.23) 1(4484.16,5996.35) 1(4484.16,6000.47) 1(4484.16,5418.07) 1(4484.16,5422.19) 1(4484.16,5426.31) 1(4484.16,5430.43) 1(4484.16,5434.55) 1(4484.16,5438.67) 1(4484.16,5442.79) 1(4484.16,5446.91) 1(4484.16,5451.03) 1(4484.16,5455.15) 1(4484.16,5459.27) 1(4484.16,5463.39) 1(4484.16,5467.51) 1(4484.16,5471.63) 1(4484.16,5475.75) 1(4484.16,5479.87) 1(4484.16,5483.99) 1(4484.16,5488.11) 1(4484.16,5492.23) 1(4484.16,5496.35) 1(4484.16,5500.47) 1(4573.14,4817.29) 1(4573.14,4821.41) 1(4573.14,4825.53) 1(4573.14,4829.65) 1(4573.14,4833.77) 1(4573.14,4837.89) 1(4573.14,4842.01) 1(4573.14,4846.13) 1(4573.14,4850.25) 1(4573.14,4854.37) 1(4573.14,4858.49) 1(4573.14,4862.61) 1(4573.14,4866.73) 1(4573.14,4870.85) 1(4573.14,4874.97) 1(4573.14,4879.09) 1(4573.14,4883.21) 1(4573.14,4887.33) 1(4573.14,4891.45) 1(4573.14,4895.57) 1(4573.14,4899.69) 1(4573.14,5767.29) 1(4573.14,5771.41) 1(4573.14,5775.53) 1(4573.14,5779.65) 1(4573.14,5783.77) 1(4573.14,5787.89) 1(4573.14,5792.01) 1(4573.14,5796.13) 1(4573.14,5800.25) 1(4573.14,5804.37) 1(4573.14,5808.49) 1(4573.14,5812.61) 1(4573.14,5816.73) 1(4573.14,5820.85) 1(4573.14,5824.97) 1(4573.14,5829.09) 1(4573.14,5833.21) 1(4573.14,5837.33) 1(4573.14,5841.45) 1(4573.14,5845.57) 1(4573.14,5849.69) 1(4573.92,5918.07) 1(4573.92,5922.19) 1(4573.92,5926.31) 1(4573.92,5930.43) 1(4573.92,5934.55) 1(4573.92,5938.67) 1(4573.92,5942.79) 1(4573.92,5946.91) 1(4573.92,5951.03) 1(4573.92,5955.15) 1(4573.92,5959.27) 1(4573.92,5963.39) 1(4573.92,5967.51) 1(4573.92,5971.63) 1(4573.92,5975.75) 1(4573.92,5979.87) 1(4573.92,5983.99) 1(4573.92,5988.11) 1(4573.92,5992.23) 1(4573.92,5996.35) 1(4573.92,6000.47) 1(4573.92,5418.07) 1(4573.92,5422.19) 1(4573.92,5426.31) 1(4573.92,5430.43) 1(4573.92,5434.55) 1(4573.92,5438.67) 1(4573.92,5442.79) 1(4573.92,5446.91) 1(4573.92,5451.03) 1(4573.92,5455.15) 1(4573.92,5459.27) 1(4573.92,5463.39) 1(4573.92,5467.51) 1(4573.92,5471.63) 1(4573.92,5475.75) 1(4573.92,5479.87) 1(4573.92,5483.99) 1(4573.92,5488.11) 1(4573.92,5492.23) 1(4573.92,5496.35) 1(4573.92,5500.47) 1(4578.26,4808.05) 1(4578.26,4808.05) 1(4578.26,4808.05) 1(4578.26,4808.05) 1(4578.26,4908.05) 1(4578.26,4908.05) 1(4578.26,4908.05) 1(4578.26,4908.05) 1(4578.26,5108.05) 1(4578.26,5108.05) 1(4578.26,5208.05) 1(4578.26,5208.05) 1(4578.26,5258.05) 1(4578.26,5258.05) 1(4578.26,5258.05) 1(4578.26,5258.05) 1(4578.26,5358.05) 1(4578.26,5358.05) 1(4578.26,5358.05) 1(4578.26,5358.05) 1(4578.26,5408.05) 1(4578.26,5408.05) 1(4578.26,5508.05) 1(4578.26,5508.05) 1(4578.26,5758.05) 1(4578.26,5758.05) 1(4578.26,5758.05) 1(4578.26,5758.05) 1(4578.26,5858.05) 1(4578.26,5858.05) 1(4578.26,5858.05) 1(4578.26,5858.05) 1(4578.26,5908.05) 1(4578.26,5908.05) 1(4578.26,5908.05) 1(4578.26,5908.05) 1(4578.26,6008.05) 1(4578.26,6008.05) 1(4578.26,6008.05) 1(4578.26,6008.05) 1(4578.26,6058.05) 1(4578.26,6058.05) 1(4578.26,6158.05) 1(4578.26,6158.05) 1(4578.26,6208.05) 1(4578.26,6208.05) 1(4578.26,6308.05) 1(4578.26,6308.05) 1(4580.04,6363.05) 1(4580.04,6363.05) 1(4580.04,6463.05) 1(4580.04,6463.05) 1(5026.82,1347.78) 1(5026.82,1497.78) 1(5026.82,1497.78) 1(5026.82,1497.78) 1(5026.82,1497.78) 1(5026.82,1497.78) 1(5027.04,838.73) 1(5027.04,838.73) 1(5032.83,625.61) 1(5032.83,625.61) 1(5033.05,-33.45) 1(5033.05,-33.45) 1(5053.46,6533.25) 1(5053.46,6683.25) 1(5153.03,6058.05) 1(5153.03,6058.05) 1(5153.03,6158.05) 1(5153.03,6158.05) 1(5153.03,6208.05) 1(5153.03,6208.05) 1(5153.03,6308.05) 1(5153.03,6308.05) 1(5153.03,6358.05) 1(5153.03,6358.05) 1(5153.03,6458.05) 1(5153.03,6458.05) 1(5153.46,5108.05) 1(5153.46,5108.05) 1(5153.46,5108.05) 1(5153.46,5108.05) 1(5153.46,5208.05) 1(5153.46,5208.05) 1(5153.46,5208.05) 1(5153.46,5208.05) 1(5153.46,5258.05) 1(5153.46,5258.05) 1(5153.46,5358.05) 1(5153.46,5358.05) 1(5153.46,5408.05) 1(5153.46,5408.05) 1(5153.46,5508.05) 1(5153.46,5508.05) 1(5153.46,5758.05) 1(5153.46,5758.05) 1(5153.46,5858.05) 1(5153.46,5858.05) 1(5153.46,5908.05) 1(5153.46,5908.05) 1(5153.46,6008.05) 1(5153.46,6008.05) 1(5158.58,5117.29) 1(5158.58,5121.41) 1(5158.58,5125.53) 1(5158.58,5129.65) 1(5158.58,5133.77) 1(5158.58,5137.89) 1(5158.58,5142.01) 1(5158.58,5146.13) 1(5158.58,5150.25) 1(5158.58,5154.37) 1(5158.58,5158.49) 1(5158.58,5162.61) 1(5158.58,5166.73) 1(5158.58,5170.85) 1(5158.58,5174.97) 1(5158.58,5179.09) 1(5158.58,5183.21) 1(5158.58,5187.33) 1(5158.58,5191.45) 1(5158.58,5195.57) 1(5158.58,5199.69) 1(5248.34,5117.29) 1(5248.34,5121.41) 1(5248.34,5125.53) 1(5248.34,5129.65) 1(5248.34,5133.77) 1(5248.34,5137.89) 1(5248.34,5142.01) 1(5248.34,5146.13) 1(5248.34,5150.25) 1(5248.34,5154.37) 1(5248.34,5158.49) 1(5248.34,5162.61) 1(5248.34,5166.73) 1(5248.34,5170.85) 1(5248.34,5174.97) 1(5248.34,5179.09) 1(5248.34,5183.21) 1(5248.34,5187.33) 1(5248.34,5191.45) 1(5248.34,5195.57) 1(5248.34,5199.69) 1(5253.03,6058.05) 1(5253.03,6058.05) 1(5253.03,6158.05) 1(5253.03,6158.05) 1(5253.03,6208.05) 1(5253.03,6208.05) 1(5253.03,6308.05) 1(5253.03,6308.05) 1(5253.03,6358.05) 1(5253.03,6358.05) 1(5253.03,6458.05) 1(5253.03,6458.05) 1(5253.46,5108.05) 1(5253.46,5108.05) 1(5253.46,5108.05) 1(5253.46,5108.05) 1(5253.46,5208.05) 1(5253.46,5208.05) 1(5253.46,5208.05) 1(5253.46,5208.05) 1(5253.46,5258.05) 1(5253.46,5258.05) 1(5253.46,5358.05) 1(5253.46,5358.05) 1(5253.46,5408.05) 1(5253.46,5408.05) 1(5253.46,5508.05) 1(5253.46,5508.05) 1(5253.46,5758.05) 1(5253.46,5758.05) 1(5253.46,5858.05) 1(5253.46,5858.05) 1(5253.46,5908.05) 1(5253.46,5908.05) 1(5253.46,6008.05) 1(5253.46,6008.05) 1(5725.25,-33.37) 1(5725.25,-33.37) 1(5726.04,625.69) 1(5726.04,625.69) 1(5726.04,625.69) 1(5726.82,838.73) 1(5726.82,1347.78) 1(5726.82,1497.78) 1(5726.82,1497.78) 1(5726.82,1497.78) 1(5728.26,5532.06) 1(5728.26,5683.64) 1(5778.26,5758.05) 1(5778.26,5758.05) 1(5778.26,5858.05) 1(5778.26,5858.05) 1(5778.26,5908.05) 1(5778.26,5908.05) 1(5778.26,6008.05) 1(5778.26,6008.05) 1(5778.38,6358.54) 1(5778.38,6358.54) 1(5778.38,6458.54) 1(5778.38,6458.54) 1(5779.02,6058.44) 1(5779.02,6058.44) 1(5779.02,6158.44) 1(5779.02,6158.44) 1(5779.02,6208.44) 1(5779.02,6208.44) 1(5779.02,6308.44) 1(5779.02,6308.44) 1(5779.02,6358.44) 1(5779.02,6358.44) 1(5779.02,6358.44) 1(5779.02,6358.44) 1(5779.02,6458.44) 1(5779.02,6458.44) 1(5779.02,6458.44) 1(5779.02,6458.44) 1(5784.28,6368.56) 1(5784.28,6372.68) 1(5784.28,6376.8) 1(5784.28,6380.92) 1(5784.28,6385.04) 1(5784.28,6389.16) 1(5784.28,6393.28) 1(5784.28,6397.4) 1(5784.28,6401.52) 1(5784.28,6405.64) 1(5784.28,6409.76) 1(5784.28,6413.88) 1(5784.28,6418) 1(5784.28,6422.12) 1(5784.28,6426.24) 1(5784.28,6430.36) 1(5784.28,6434.48) 1(5784.28,6438.6) 1(5784.28,6442.72) 1(5784.28,6446.84) 1(5784.28,6450.96) 1(5874.04,6368.56) 1(5874.04,6372.68) 1(5874.04,6376.8) 1(5874.04,6380.92) 1(5874.04,6385.04) 1(5874.04,6389.16) 1(5874.04,6393.28) 1(5874.04,6397.4) 1(5874.04,6401.52) 1(5874.04,6405.64) 1(5874.04,6409.76) 1(5874.04,6413.88) 1(5874.04,6418) 1(5874.04,6422.12) 1(5874.04,6426.24) 1(5874.04,6430.36) 1(5874.04,6434.48) 1(5874.04,6438.6) 1(5874.04,6442.72) 1(5874.04,6446.84) 1(5874.04,6450.96) 1(5878.26,5758.05) 1(5878.26,5758.05) 1(5878.26,5858.05) 1(5878.26,5858.05) 1(5878.26,5908.05) 1(5878.26,5908.05) 1(5878.26,6008.05) 1(5878.26,6008.05) 1(5878.38,6358.54) 1(5878.38,6358.54) 1(5878.38,6458.54) 1(5878.38,6458.54) 1(5879.02,6058.44) 1(5879.02,6058.44) 1(5879.02,6158.44) 1(5879.02,6158.44) 1(5879.02,6208.44) 1(5879.02,6208.44) 1(5879.02,6308.44) 1(5879.02,6308.44) 1(5879.02,6358.44) 1(5879.02,6358.44) 1(5879.02,6358.44) 1(5879.02,6358.44) 1(5879.02,6458.44) 1(5879.02,6458.44) 1(5879.02,6458.44) 1(5879.02,6458.44) 1(5915.58,6533.25) 1(5915.58,6682.95) 1(6153.46,5258.05) 1(6153.46,5258.05) 1(6153.46,5358.05) 1(6153.46,5358.05) 1(6153.46,5408.05) 1(6153.46,5408.05) 1(6153.46,5408.05) 1(6153.46,5408.05) 1(6153.46,5508.05) 1(6153.46,5508.05) 1(6153.46,5508.05) 1(6153.46,5508.05) 1(6159.36,5268.07) 1(6159.36,5272.19) 1(6159.36,5276.31) 1(6159.36,5280.43) 1(6159.36,5284.55) 1(6159.36,5288.67) 1(6159.36,5292.79) 1(6159.36,5296.91) 1(6159.36,5301.03) 1(6159.36,5305.15) 1(6159.36,5309.27) 1(6159.36,5313.39) 1(6159.36,5317.51) 1(6159.36,5321.63) 1(6159.36,5325.75) 1(6159.36,5329.87) 1(6159.36,5333.99) 1(6159.36,5338.11) 1(6159.36,5342.23) 1(6159.36,5346.35) 1(6159.36,5350.47) 1(6249.12,5268.07) 1(6249.12,5272.19) 1(6249.12,5276.31) 1(6249.12,5280.43) 1(6249.12,5284.55) 1(6249.12,5288.67) 1(6249.12,5292.79) 1(6249.12,5296.91) 1(6249.12,5301.03) 1(6249.12,5305.15) 1(6249.12,5309.27) 1(6249.12,5313.39) 1(6249.12,5317.51) 1(6249.12,5321.63) 1(6249.12,5325.75) 1(6249.12,5329.87) 1(6249.12,5333.99) 1(6249.12,5338.11) 1(6249.12,5342.23) 1(6249.12,5346.35) 1(6249.12,5350.47) 1(6253.46,5258.05) 1(6253.46,5258.05) 1(6253.46,5358.05) 1(6253.46,5358.05) 1(6253.46,5408.05) 1(6253.46,5408.05) 1(6253.46,5408.05) 1(6253.46,5408.05) 1(6253.46,5508.05) 1(6253.46,5508.05) 1(6253.46,5508.05) 1(6253.46,5508.05) 1(6278.26,5532.85) 1(6278.26,5683.25) 1(6326.04,625.69) 1(6326.04,625.69) 1(6326.04,625.69) 1(6326.04,625.69) 1(6326.26,-33.37) 1(6326.26,-33.37) 1(6326.82,838.73) 1(6326.82,1347.78) 1(6326.82,1497.78) 1(6326.82,1497.78) 1(6326.82,1497.78) 1(6428.26,6533.25) 1(6428.26,6683.25) 1(6552.64,5758.05) 1(6552.64,5758.05) 1(6552.64,5858.05) 1(6552.64,5858.05) 1(6552.64,5908.05) 1(6552.64,5908.05) 1(6552.64,6008.05) 1(6552.64,6008.05) 1(6552.64,6058.05) 1(6552.64,6058.05) 1(6552.64,6158.05) 1(6552.64,6158.05) 1(6553.03,6208.05) 1(6553.03,6208.05) 1(6553.03,6308.05) 1(6553.03,6308.05) 1(6553.03,6358.05) 1(6553.03,6358.05) 1(6553.03,6458.05) 1(6553.03,6458.05) 1(6652.64,5758.05) 1(6652.64,5758.05) 1(6652.64,5858.05) 1(6652.64,5858.05) 1(6652.64,5908.05) 1(6652.64,5908.05) 1(6652.64,6008.05) 1(6652.64,6008.05) 1(6652.64,6058.05) 1(6652.64,6058.05) 1(6652.64,6158.05) 1(6652.64,6158.05) 1(6653.03,6208.05) 1(6653.03,6208.05) 1(6653.03,6308.05) 1(6653.03,6308.05) 1(6653.03,6358.05) 1(6653.03,6358.05) 1(6653.03,6458.05) 1(6653.03,6458.05) 1(6879.76,6533.25) 1(6879.76,6683.25) 1(7075.26,-33.37) 1(7075.26,-33.37) 1(7076.04,625.69) 1(7076.04,625.69) 1(7076.04,625.69) 1(7076.04,625.69) 1(7076.82,1347.78) 1(7076.82,1497.78) 1(7076.82,1497.78) 1(7076.82,1497.78) 1(7076.82,1497.78) 1(7076.82,1497.78) 1(7077.04,838.73) 1(7077.04,838.73) 1(7128.26,4808.05) 1(7128.26,4808.05) 1(7128.26,4908.05) 1(7128.26,4908.05) 1(7128.26,5258.05) 1(7128.26,5258.05) 1(7128.26,5358.05) 1(7128.26,5358.05) 1(7128.26,5408.05) 1(7128.26,5408.05) 1(7128.26,5508.05) 1(7128.26,5508.05) 1(7228.26,4808.05) 1(7228.26,4808.05) 1(7228.26,4908.05) 1(7228.26,4908.05) 1(7228.26,5258.05) 1(7228.26,5258.05) 1(7228.26,5358.05) 1(7228.26,5358.05) 1(7228.26,5408.05) 1(7228.26,5408.05) 1(7228.26,5508.05) 1(7228.26,5508.05) 1(7240.07,6054.9) 1(7240.07,6054.9) 1(7240.07,6054.9) 1(7240.07,6054.9) 1(7240.07,6154.9) 1(7240.07,6154.9) 1(7240.07,6154.9) 1(7240.07,6154.9) 1(7240.07,6354.9) 1(7240.07,6354.9) 1(7240.07,6454.9) 1(7240.07,6454.9) 1(7245.19,6064.14) 1(7245.19,6068.26) 1(7245.19,6072.38) 1(7245.19,6076.5) 1(7245.19,6080.62) 1(7245.19,6084.74) 1(7245.19,6088.86) 1(7245.19,6092.98) 1(7245.19,6097.1) 1(7245.19,6101.22) 1(7245.19,6105.34) 1(7245.19,6109.46) 1(7245.19,6113.58) 1(7245.19,6117.7) 1(7245.19,6121.82) 1(7245.19,6125.94) 1(7245.19,6130.06) 1(7245.19,6134.18) 1(7245.19,6138.3) 1(7245.19,6142.42) 1(7245.19,6146.54) 1(7334.95,6064.14) 1(7334.95,6068.26) 1(7334.95,6072.38) 1(7334.95,6076.5) 1(7334.95,6080.62) 1(7334.95,6084.74) 1(7334.95,6088.86) 1(7334.95,6092.98) 1(7334.95,6097.1) 1(7334.95,6101.22) 1(7334.95,6105.34) 1(7334.95,6109.46) 1(7334.95,6113.58) 1(7334.95,6117.7) 1(7334.95,6121.82) 1(7334.95,6125.94) 1(7334.95,6130.06) 1(7334.95,6134.18) 1(7334.95,6138.3) 1(7334.95,6142.42) 1(7334.95,6146.54) 1(7340.07,6054.9) 1(7340.07,6054.9) 1(7340.07,6054.9) 1(7340.07,6054.9) 1(7340.07,6154.9) 1(7340.07,6154.9) 1(7340.07,6154.9) 1(7340.07,6154.9) 1(7340.07,6354.9) 1(7340.07,6354.9) 1(7340.07,6454.9) 1(7340.07,6454.9) 1(7526.04,-33.37) 1(7526.04,76.48) 1(7526.04,186.32) 1(7526.04,296.16) 1(7526.04,406) 1(7526.04,515.85) 1(7526.04,625.69) 1(7526.04,625.69) 1(7550.84,-33.37) 1(7550.84,-33.37) 1(7550.84,-33.37) 1(7550.84,76.48) 1(7550.84,186.32) 1(7550.84,296.16) 1(7550.84,406) 1(7550.84,515.85) 1(7550.84,625.69) 1(7550.84,625.69) 1(7550.84,625.69) 1(7550.84,625.69) 1(7551.62,838.73) 1(7551.62,838.73) 1(7551.62,948.57) 1(7551.62,1058.41) 1(7551.62,1168.25) 1(7551.62,1278.1) 1(7551.62,1387.94) 1(7551.62,1497.78) 1(7551.62,1497.78) 1(7551.62,1497.78) 1(7828.26,-285.31) 1(7828.26,-285.31) 1(7828.26,1711.69) 1(7828.26,4034.69) 1(7828.26,4478.91) 1(7828.26,4626.16) 1(7828.26,4780.1) 1(7828.26,4782.85) 1(7828.26,4782.85) 1(7828.26,4932.85) 1(7828.26,5082.85) 1(7828.26,5232.85) 1(7828.26,5382.85) 1(7828.26,5532.85) 1(7828.26,5683.25) 1(7828.26,5733.25) 1(7828.26,5883.25) 1(7828.26,6033.25) 1(7828.26,6183.25) 1(7828.26,6333.25) 1(7828.26,6483.25) 1(7828.26,6533.25) 1(7828.26,6683.25) 1(7828.26,6683.25)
